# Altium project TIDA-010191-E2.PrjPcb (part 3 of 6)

## Sheet TIDA-010191-E2_CDCLVP111.SchDoc: LMK0482x
size 558 x 431 mm; Date: Not shown in title block; ApprovedBy: Not shown in title block; CheckedBy: Not shown in title block; Author: Not shown in title block; CompanyName: Not shown in title block; DrawnBy: Avinash N; Engineer: Not shown in title block; Organization: Not shown in title block; Address1: Not shown in title block; Address2: Not shown in title block; Address3: Not shown in title block; Address4: Not shown in title block; DocumentNumber: 3; Revision: Use project parameter SCH_Rev; SheetNumber: 3; SheetTotal: 9; PageSetup: Record=PageOptions¦CenterHorizontal=True¦CenterVertical=True¦PrintScale=1.00¦XCorrection=1.00¦YCorrection=1.00¦PrintKind=0¦BorderSize=5000000¦LeftOffset=0¦BottomOffset=0¦Orientation=2¦PaperLength=1000¦PaperWidth=1000¦Scale=100¦PaperSource=15¦PrintQuality=600¦MediaType=1¦DitherType=10¦PaperKind=Letter¦PrintScaleMode=1
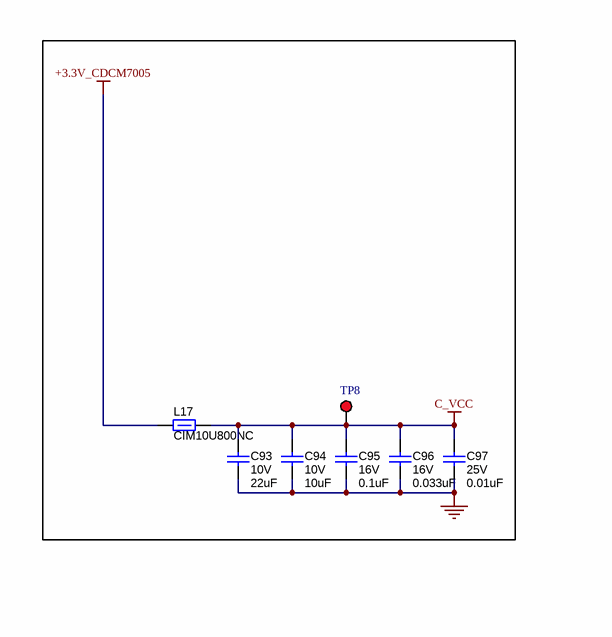
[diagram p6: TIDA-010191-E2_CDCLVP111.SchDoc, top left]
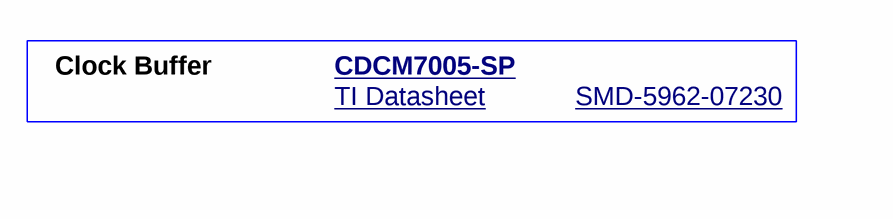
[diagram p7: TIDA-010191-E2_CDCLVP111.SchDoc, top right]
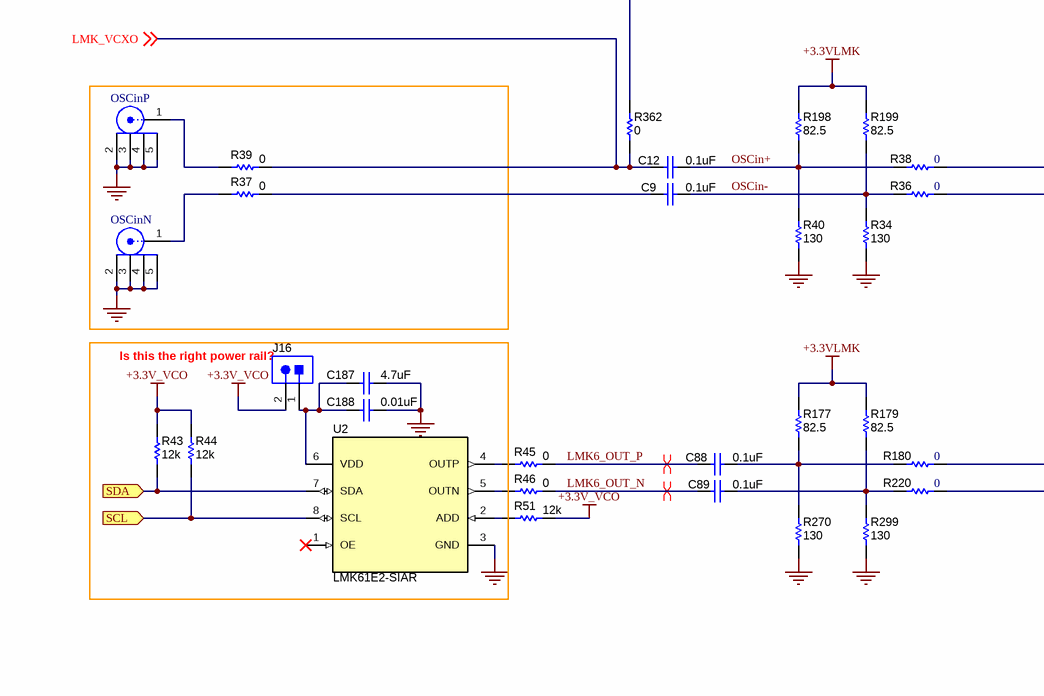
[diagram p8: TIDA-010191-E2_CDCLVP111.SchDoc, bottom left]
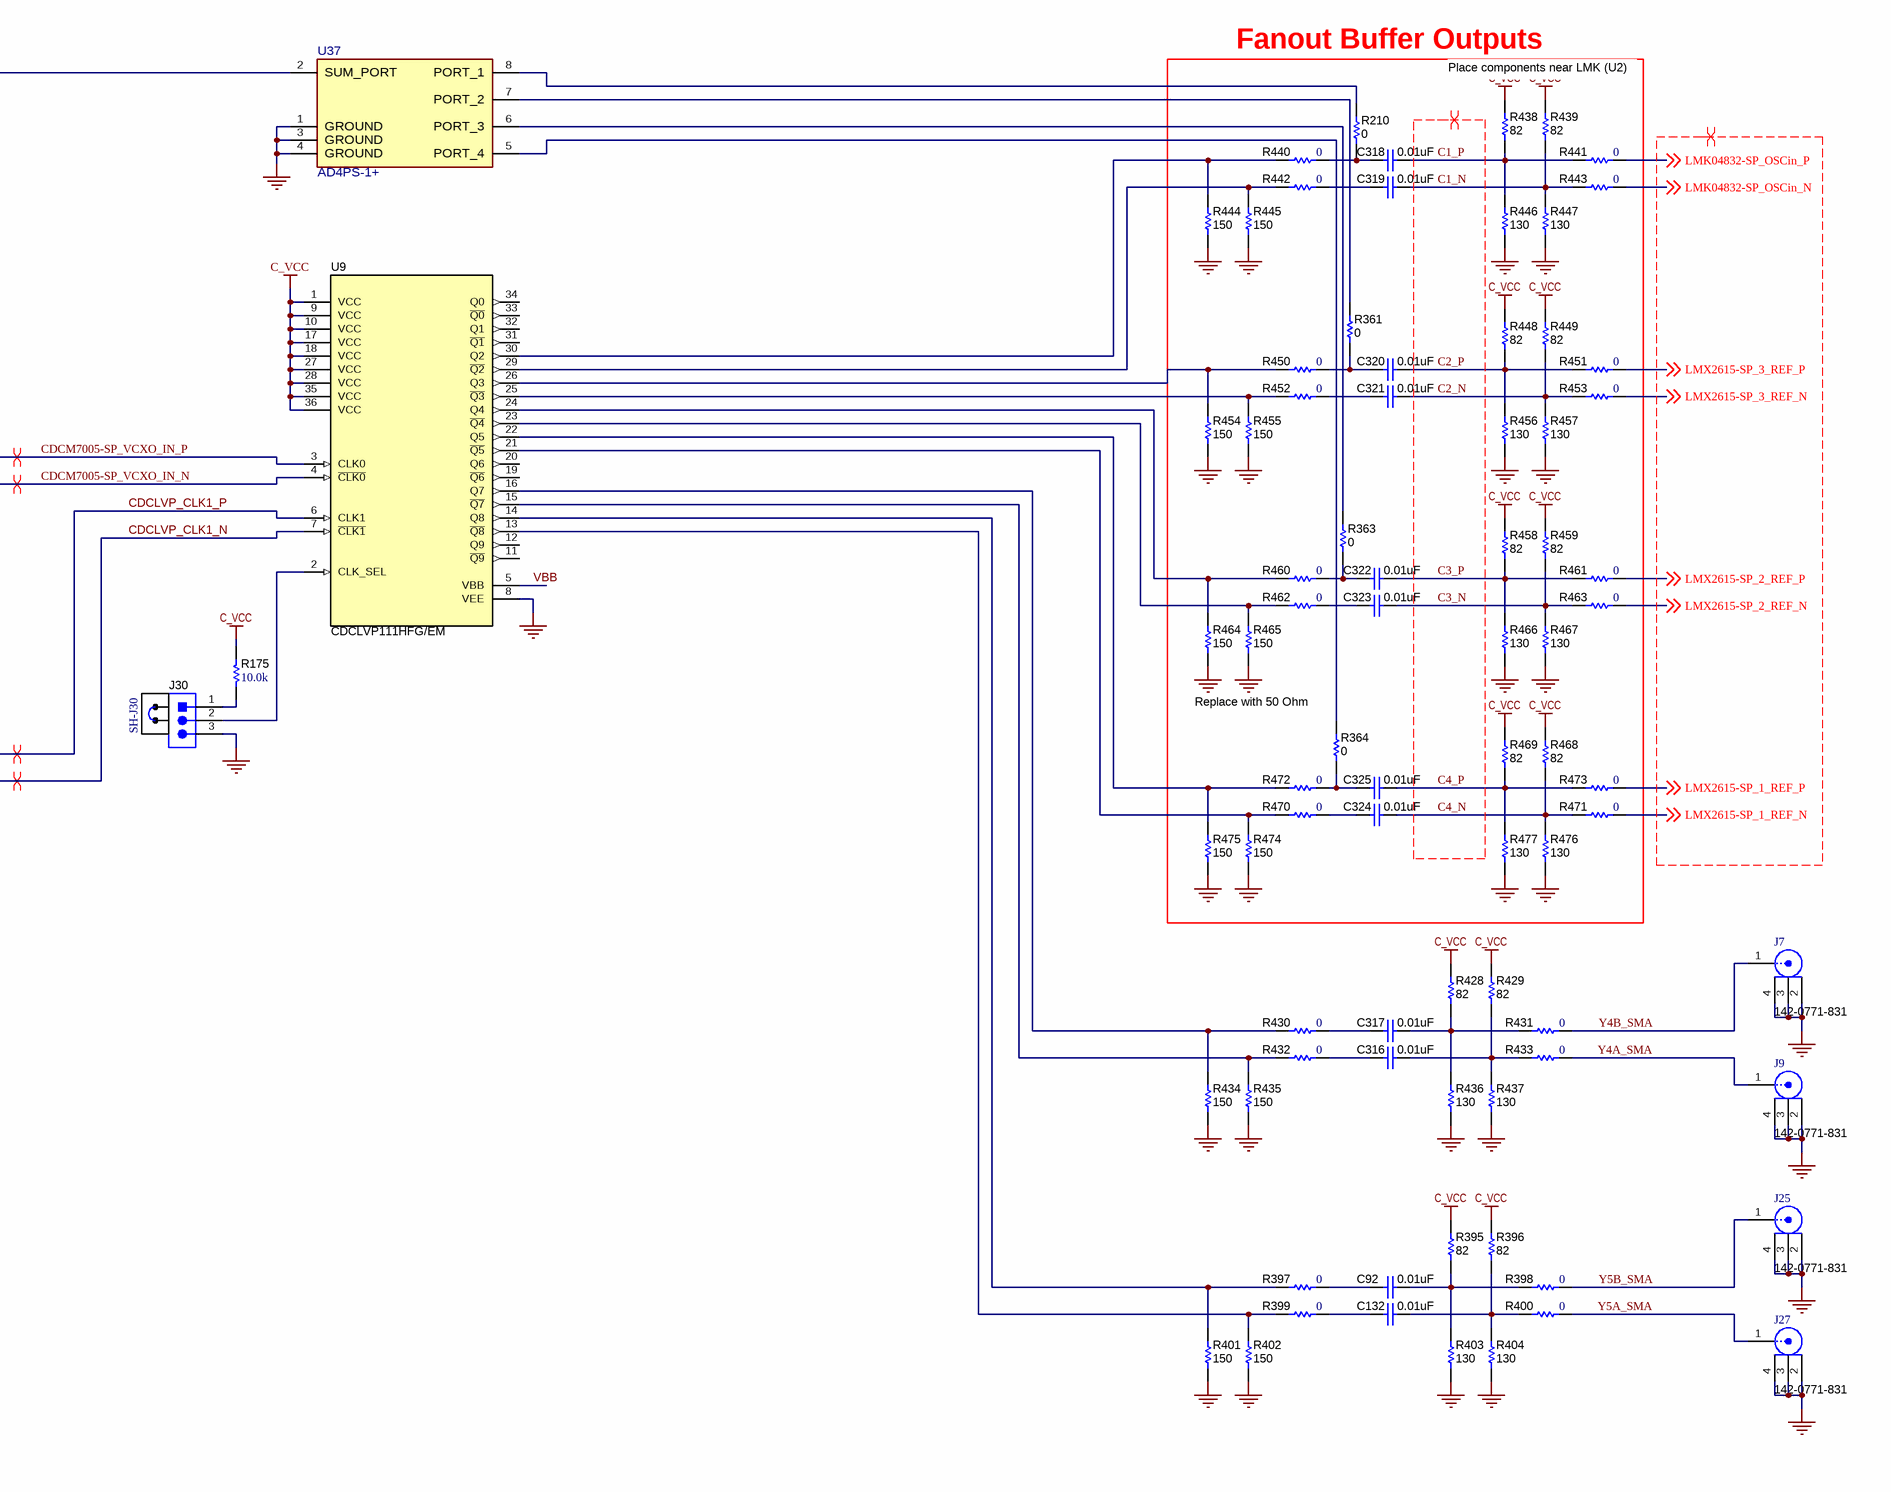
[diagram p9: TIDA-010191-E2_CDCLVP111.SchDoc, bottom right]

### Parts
C9  ValueDisplayed: 0.1uF  [0402]  (hidden comment: Capacitor)
C12  ValueDisplayed: 0.1uF  [0402]  (hidden comment: Capacitor)
C88  ValueDisplayed: 0.1uF  [0402]  (hidden comment: Capacitor)
C89  ValueDisplayed: 0.1uF  [0402]  (hidden comment: Capacitor)
C92  ValueDisplayed: 0.01uF  [0402_065]  (hidden comment: CMP-0006210-2)
C93  VDC_V: 10V  ValueDisplayed: 22uF  [1210_270]  (hidden comment: GRM32ER61A226KE20L)
C94  VDC_V: 10V  ValueDisplayed: 10uF  [1210_210]  (hidden comment: C1210C106K8PACTU)
C95  VDC_V: 16V  ValueDisplayed: 0.1uF  [0402]  (hidden comment: 885012105016)
C96  VDC_V: 16V  ValueDisplayed: 0.033uF  [0402]  (hidden comment: GRM155R61C333KA01D)
C97  VDC_V: 25V  ValueDisplayed: 0.01uF  [0402]  (hidden comment: GCM155R71E103KA37D)
C132  ValueDisplayed: 0.01uF  [0402_065]  (hidden comment: CMP-0006210-2)
C187  ValueDisplayed: 4.7uF  [0402]  (hidden comment: Capacitor)
C188  ValueDisplayed: 0.01uF  [0402]  (hidden comment: Capacitor)
C316  ValueDisplayed: 0.01uF  [0402_065]  (hidden comment: CMP-0006210-2)
C317  ValueDisplayed: 0.01uF  [0402_065]  (hidden comment: CMP-0006210-2)
C318  ValueDisplayed: 0.01uF  [0402_065]  (hidden comment: CMP-0006210-2)
C319  ValueDisplayed: 0.01uF  [0402_065]  (hidden comment: CMP-0006210-2)
C320  ValueDisplayed: 0.01uF  [0402_065]  (hidden comment: CMP-0006210-2)
C321  ValueDisplayed: 0.01uF  [0402_065]  (hidden comment: CMP-0006210-2)
C322  ValueDisplayed: 0.01uF  [0402_065]  (hidden comment: CMP-0006210-2)
C323  ValueDisplayed: 0.01uF  [0402_065]  (hidden comment: CMP-0006210-2)
C324  ValueDisplayed: 0.01uF  [0402_065]  (hidden comment: CMP-0006210-2)
C325  ValueDisplayed: 0.01uF  [0402_065]  (hidden comment: CMP-0006210-2)
J7  142-0771-831  [Johnson_142-0771-831]
J9  142-0771-831  [Johnson_142-0771-831]
J16  HTSW-102-07-G-S  [Samtec_HTSW-102-07-G-S]  (value not drawn)
J25  142-0771-831  [Johnson_142-0771-831]
J27  142-0771-831  [Johnson_142-0771-831]
J30  HTSW-103-07-G-S  [Samtec_HTSW-103-07-G-S]  (value not drawn)
L17  CIM10U800NC  [0603]
OSCinN  SMA_Contact1_GND2345  [Emerson_142-0701-851]  (value not drawn)
OSCinP  SMA_Contact1_GND2345  [Emerson_142-0701-851]  (value not drawn)
R34  ValueDisplayed: 130  [0402]  (hidden comment: Resistor)
R36  ValueDisplayed: 0  [0402]  (hidden comment: ERJ-2GE0R00X)
R37  ValueDisplayed: 0  [0402]  (hidden comment: Resistor)
R38  ValueDisplayed: 0  [0402]  (hidden comment: ERJ-2GE0R00X)
R39  ValueDisplayed: 0  [0402]  (hidden comment: Resistor)
R40  ValueDisplayed: 130  [0402]  (hidden comment: Resistor)
R43  ValueDisplayed: 12k  [0402]  (hidden comment: Resistor)
R44  ValueDisplayed: 12k  [0402]  (hidden comment: Resistor)
R45  ValueDisplayed: 0  [0402]  (hidden comment: Resistor)
R46  ValueDisplayed: 0  [0402]  (hidden comment: Resistor)
R51  ValueDisplayed: 12k  [0402]  (hidden comment: Resistor)
R175  ValueDisplayed: 10.0k  [0402]  (hidden comment: ERJ-2RKF1002X)
R177  ValueDisplayed: 82.5  [0402]  (hidden comment: CRCW040282R5FKED)
R179  ValueDisplayed: 82.5  [0402]  (hidden comment: CRCW040282R5FKED)
R180  ValueDisplayed: 0  [0402]  (hidden comment: ERJ-2GE0R00X)
R198  ValueDisplayed: 82.5  [0402]  (hidden comment: CRCW040282R5FKED)
R199  ValueDisplayed: 82.5  [0402]  (hidden comment: CRCW040282R5FKED)
R210  ValueDisplayed: 0  [0201]  (hidden comment: ERJ-1GN0R00C)
R220  ValueDisplayed: 0  [0402]  (hidden comment: ERJ-2GE0R00X)
R270  ValueDisplayed: 130  [0402]  (hidden comment: Resistor)
R299  ValueDisplayed: 130  [0402]  (hidden comment: Resistor)
R361  ValueDisplayed: 0  [0201]  (hidden comment: ERJ-1GN0R00C)
R362  ValueDisplayed: 0  [0201]  (hidden comment: ERJ-1GN0R00C)
R363  ValueDisplayed: 0  [0201]  (hidden comment: ERJ-1GN0R00C)
R364  ValueDisplayed: 0  [0201]  (hidden comment: ERJ-1GN0R00C)
R395  ValueDisplayed: 82  [0402]  (hidden comment: CRCW040282R0JNED)
R396  ValueDisplayed: 82  [0402]  (hidden comment: CRCW040282R0JNED)
R397  ValueDisplayed: 0  [0402]  (hidden comment: ERJ-2GE0R00X)
R398  ValueDisplayed: 0  [0402]  (hidden comment: ERJ-2GE0R00X)
R399  ValueDisplayed: 0  [0402]  (hidden comment: ERJ-2GE0R00X)
R400  ValueDisplayed: 0  [0402]  (hidden comment: ERJ-2GE0R00X)
R401  ValueDisplayed: 150  [0402]  (hidden comment: CRCW0402150RFKED)
R402  ValueDisplayed: 150  [0402]  (hidden comment: CRCW0402150RFKED)
R403  ValueDisplayed: 130  [0402]  (hidden comment: CRCW0402130RFKED)
R404  ValueDisplayed: 130  [0402]  (hidden comment: CRCW0402130RFKED)
R428  ValueDisplayed: 82  [0402]  (hidden comment: CRCW040282R0JNED)
R429  ValueDisplayed: 82  [0402]  (hidden comment: CRCW040282R0JNED)
R430  ValueDisplayed: 0  [0402]  (hidden comment: ERJ-2GE0R00X)
R431  ValueDisplayed: 0  [0402]  (hidden comment: ERJ-2GE0R00X)
R432  ValueDisplayed: 0  [0402]  (hidden comment: ERJ-2GE0R00X)
R433  ValueDisplayed: 0  [0402]  (hidden comment: ERJ-2GE0R00X)
R434  ValueDisplayed: 150  [0402]  (hidden comment: CRCW0402150RFKED)
R435  ValueDisplayed: 150  [0402]  (hidden comment: CRCW0402150RFKED)
R436  ValueDisplayed: 130  [0402]  (hidden comment: CRCW0402130RFKED)
R437  ValueDisplayed: 130  [0402]  (hidden comment: CRCW0402130RFKED)
R438  ValueDisplayed: 82  [0402]  (hidden comment: CRCW040282R0JNED)
R439  ValueDisplayed: 82  [0402]  (hidden comment: CRCW040282R0JNED)
R440  ValueDisplayed: 0  [0402]  (hidden comment: ERJ-2GE0R00X)
R441  ValueDisplayed: 0  [0402]  (hidden comment: ERJ-2GE0R00X)
R442  ValueDisplayed: 0  [0402]  (hidden comment: ERJ-2GE0R00X)
R443  ValueDisplayed: 0  [0402]  (hidden comment: ERJ-2GE0R00X)
R444  ValueDisplayed: 150  [0402]  (hidden comment: CRCW0402150RFKED)
R445  ValueDisplayed: 150  [0402]  (hidden comment: CRCW0402150RFKED)
R446  ValueDisplayed: 130  [0402]  (hidden comment: CRCW0402130RFKED)
R447  ValueDisplayed: 130  [0402]  (hidden comment: CRCW0402130RFKED)
R448  ValueDisplayed: 82  [0402]  (hidden comment: CRCW040282R0JNED)
R449  ValueDisplayed: 82  [0402]  (hidden comment: CRCW040282R0JNED)
R450  ValueDisplayed: 0  [0402]  (hidden comment: ERJ-2GE0R00X)
R451  ValueDisplayed: 0  [0402]  (hidden comment: ERJ-2GE0R00X)
R452  ValueDisplayed: 0  [0402]  (hidden comment: ERJ-2GE0R00X)
R453  ValueDisplayed: 0  [0402]  (hidden comment: ERJ-2GE0R00X)
R454  ValueDisplayed: 150  [0402]  (hidden comment: CRCW0402150RFKED)
R455  ValueDisplayed: 150  [0402]  (hidden comment: CRCW0402150RFKED)
R456  ValueDisplayed: 130  [0402]  (hidden comment: CRCW0402130RFKED)
R457  ValueDisplayed: 130  [0402]  (hidden comment: CRCW0402130RFKED)
R458  ValueDisplayed: 82  [0402]  (hidden comment: CRCW040282R0JNED)
R459  ValueDisplayed: 82  [0402]  (hidden comment: CRCW040282R0JNED)
R460  ValueDisplayed: 0  [0402]  (hidden comment: ERJ-2GE0R00X)
R461  ValueDisplayed: 0  [0402]  (hidden comment: ERJ-2GE0R00X)
R462  ValueDisplayed: 0  [0402]  (hidden comment: ERJ-2GE0R00X)
R463  ValueDisplayed: 0  [0402]  (hidden comment: ERJ-2GE0R00X)
R464  ValueDisplayed: 150  [0402]  (hidden comment: CRCW0402150RFKED)
R465  ValueDisplayed: 150  [0402]  (hidden comment: CRCW0402150RFKED)
R466  ValueDisplayed: 130  [0402]  (hidden comment: CRCW0402130RFKED)
R467  ValueDisplayed: 130  [0402]  (hidden comment: CRCW0402130RFKED)
R468  ValueDisplayed: 82  [0402]  (hidden comment: CRCW040282R0JNED)
R469  ValueDisplayed: 82  [0402]  (hidden comment: CRCW040282R0JNED)
R470  ValueDisplayed: 0  [0402]  (hidden comment: ERJ-2GE0R00X)
R471  ValueDisplayed: 0  [0402]  (hidden comment: ERJ-2GE0R00X)
R472  ValueDisplayed: 0  [0402]  (hidden comment: ERJ-2GE0R00X)
R473  ValueDisplayed: 0  [0402]  (hidden comment: ERJ-2GE0R00X)
R474  ValueDisplayed: 150  [0402]  (hidden comment: CRCW0402150RFKED)
R475  ValueDisplayed: 150  [0402]  (hidden comment: CRCW0402150RFKED)
R476  ValueDisplayed: 130  [0402]  (hidden comment: CRCW0402130RFKED)
R477  ValueDisplayed: 130  [0402]  (hidden comment: CRCW0402130RFKED)
SH-J30  SPC02SYAN  [SPC02SYAN]  (value not drawn)
TP8  5000  [Keystone5000]  (value not drawn)
U2  PartNumber: LMK61E2-SIAR  [SIA0008B]  (hidden comment: CMP-0075884-1)
U9  CDCLVP111HFG/EM  [HFG0036A_Custom_A]
U37  AD4PS-1+  [FP-AD4PS-1+_SMT8-MFG]

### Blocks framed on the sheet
Is this the right power rail?: C187 C188 J16 R43 R44 U2

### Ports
SCL (in), SDA (in)

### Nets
+3.3V_CDCM7005: L17.1
+3.3V_VCO: J16.2 R43.2 R44.2 R51.1
+3.3VLMK: R177.1 R179.1 R198.1 R199.1
C_VCC: C93.1 C94.1 C95.1 C96.1 C97.1 L17.2 R175.2 R395.2 R396.2 R428.2 R429.2 R438.2 R439.2 R448.2 R449.2 R458.2 R459.2 R468.2 R469.2 TP8.1 U9.1(VCC) U9.9(VCC) U9.10(VCC) U9.17(VCC) U9.18(VCC) U9.27(VCC) U9.28(VCC) U9.35(VCC) U9.36(VCC)
GND: C93.2 C94.2 C95.2 C96.2 C97.2 C187.1 C188.1 J7.2 J7.3 J7.4 J9.2 J9.3 J9.4 J25.2 J25.3 J25.4 J27.2 J27.3 J27.4 J30.3 OSCinN.2 OSCinN.3 OSCinN.4 OSCinN.5 OSCinP.2 OSCinP.3 OSCinP.4 OSCinP.5 R34.2 R40.2 R270.2 R299.2 R401.1 R402.1 R403.1 R404.1 R434.1 R435.1 R436.1 R437.1 R444.1 R445.1 R446.1 R447.1 R454.1 R455.1 R456.1 R457.1 R464.1 R465.1 R466.1 R467.1 R474.1 R475.1 R476.1 R477.1 U2.3(GND) U9.8(VEE) U37.1(GROUND) U37.3(GROUND) U37.4(GROUND)
C1_N: C319.1 R439.1 R443.1 R447.2
C1_P: C318.1 R438.1 R441.1 R446.2
C2_N: C321.1 R449.1 R453.1 R457.2
C2_P: C320.1 R448.1 R451.1 R456.2
C3_N: C323.1 R459.1 R463.1 R467.2
C3_P: C322.1 R458.1 R461.1 R466.2
C4_N: C324.1 R468.1 R471.1 R476.2
C4_P: C325.1 R469.1 R473.1 R477.2
CDCLVP_CLK1_N: R220.2 U9.7(~{CLK1})
CDCLVP_CLK1_P: R180.2 U9.6(CLK1)
CDCM7005-SP_VCXO_IN_N: R36.2 U9.4(~{CLK0})
CDCM7005-SP_VCXO_IN_P: R38.2 U9.3(CLK0)
LMK6_OUT_N: C89.1 R46.2
LMK6_OUT_P: C88.1 R45.2
LMK04832-SP_OSCin_N: R443.2 ; off-sheet LMK04832-SP_OSCin_N  [project net LMK_OSCin_N]
LMK04832-SP_OSCin_P: R441.2 ; off-sheet LMK04832-SP_OSCin_P  [project net LMK_OSCin_P]
LMK_VCXO: C12.1 R39.2 R362.1 ; off-sheet LMK_VCXO
LMX2615-SP_1_REF_N: R471.2 ; off-sheet LMX2615-SP_1_REF_N
LMX2615-SP_1_REF_P: R473.2 ; off-sheet LMX2615-SP_1_REF_P
LMX2615-SP_2_REF_N: R463.2 ; off-sheet LMX2615-SP_2_REF_N
LMX2615-SP_2_REF_P: R461.2 ; off-sheet LMX2615-SP_2_REF_P
LMX2615-SP_3_REF_N: R453.2 ; off-sheet LMX2615-SP_3_REF_N
LMX2615-SP_3_REF_P: R451.2 ; off-sheet LMX2615-SP_3_REF_P
OSCin+: C12.2 R38.1 R40.1 R198.2
OSCin-: C9.2 R34.1 R36.1 R199.2
SCL: R44.1 U2.8(SCL) ; port SCL
SDA: R43.1 U2.7(SDA) ; port SDA
VBB: U9.5(VBB)
Y4A_SMA: J9.1 R433.2
Y4B_SMA: J7.1 R431.2
Y5A_SMA: J27.1 R400.2
Y5B_SMA: J25.1 R398.2
NetC9_1: C9.1 R37.2
NetC88_2: C88.2 R177.2 R180.1 R270.1
NetC89_2: C89.2 R179.2 R220.1 R299.1
NetC92_1: C92.1 R395.1 R398.1 R403.2
NetC92_2: C92.2 R397.2
NetC132_1: C132.1 R396.1 R400.1 R404.2
NetC132_2: C132.2 R399.2
NetC187_2: C187.2 C188.2 J16.1 U2.6(VDD)
NetC316_1: C316.1 R429.1 R433.1 R437.2
NetC316_2: C316.2 R432.2
NetC317_1: C317.1 R428.1 R431.1 R436.2
NetC317_2: C317.2 R430.2
NetC318_2: C318.2 R210.1 R440.2
NetC319_2: C319.2 R442.2
NetC320_2: C320.2 R361.1 R450.2
NetC321_2: C321.2 R452.2
NetC322_2: C322.2 R363.1 R460.2
NetC323_2: C323.2 R462.2
NetC324_2: C324.2 R470.2
NetC325_2: C325.2 R364.1 R472.2
NetJ30_1: J30.1 R175.1
NetJ30_2: J30.2 U9.2(CLK_SEL)
NetOSCinN_1: OSCinN.1 R37.1
NetOSCinP_1: OSCinP.1 R39.1
NetR45_1: R45.1 U2.4(OUTP)
NetR46_1: R46.1 U2.5(OUTN)
NetR51_2: R51.2 U2.2(ADD)
NetR210_2: R210.2 U37.8(PORT_1)
NetR361_2: R361.2 U37.7(PORT_2)
NetR362_2: R362.2 U37.2(SUM_PORT)
NetR363_2: R363.2 U37.6(PORT_3)
NetR364_2: R364.2 U37.5(PORT_4)
NetR397_1: R397.1 R401.2 U9.14(Q8)
NetR399_1: R399.1 R402.2 U9.13(~{Q8})
NetR430_1: R430.1 R434.2 U9.16(Q7)
NetR432_1: R432.1 R435.2 U9.15(~{Q7})
NetR440_1: R440.1 R444.2 U9.30(Q2)
NetR442_1: R442.1 R445.2 U9.29(~{Q2})
NetR450_1: R450.1 R454.2 U9.26(Q3)
NetR452_1: R452.1 R455.2 U9.25(~{Q3})
NetR460_1: R460.1 R464.2 U9.24(Q4)
NetR462_1: R462.1 R465.2 U9.23(~{Q4})
NetR470_1: R470.1 R474.2 U9.21(~{Q5})
NetR472_1: R472.1 R475.2 U9.22(Q5)

Not connected (* = marked no-connect by the designer): U2 1(OE)*; U9 11(~{Q9}) 12(Q9) 19(~{Q6}) 20(Q6) 31(~{Q1}) 32(Q1) 33(~{Q0}) 34(Q0)

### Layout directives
differential pair: CDCLVP_CLK1_N, CDCLVP_CLK1_P, CDCM7005-SP_VCXO_IN_N, CDCM7005-SP_VCXO_IN_P, LMK6_OUT_N, LMK6_OUT_P
differential pair; differential pair class 100ohm: C1_N, C1_P, C2_N, C2_P, C3_N, C3_P, C4_N, C4_P, LMK04832-SP_OSCin_N, LMK04832-SP_OSCin_P, LMX2615-SP_1_REF_N, LMX2615-SP_1_REF_P, LMX2615-SP_2_REF_N, LMX2615-SP_2_REF_P, LMX2615-SP_3_REF_N, LMX2615-SP_3_REF_P

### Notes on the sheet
- Clock Buffer
- TI Datasheet <http://www.ti.com/lit/gpn/cdcm7005-sp>
- CDCM7005-SP <http://www.ti.com/product/CDCM7005-SP>
- SMD-5962-07230 <https://landandmaritimeapps.dla.mil/Downloads/MilSpec/Smd/07230.pdf>
- Fanout Buffer Outputs
- Place components near LMK (U2)
- (near R364) Replace with 50 Ohm

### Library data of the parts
C9 C12 C88 C89 = CMP-0006295-2: CAP, CERM, 0.1 uF, 25 V, +/- 20%, X7R, 0402; Manufacturer: TDK; PartNumber: C1005X7R1E104M050BB; Polarized: N; TaMax_C: 125°C; TaMin_C: -55°C; VDC_V: 25V; Cap_F: 100nF; Value: 0.1uF; Value1: Unknown; U/M: EA; SizeArea_mm2: 0.5; SizeAreaWB_mm2: 3; SizeX_mm: 1; SizeZ_mm: 0.6; AEC Category: Q200
C92 C132 C316-C325 = CMP-0006210-2: CAP, CERM, 0.01 uF, 16 V, +/- 10%, X7R, 0402; PartNumber: 520L103KT16T; Manufacturer: AT Ceramics; Polarized: N; Value: 0.01uF; U/M: EA; Cap_F: 10nF; Value1: Unknown; VDC_V: 16V; TaMin_C: -55°C; TaMax_C: 125°C; Cap_Case: 0402; AEC Category: Q200; SizeArea_mm2: 0.5; SizeAreaWB_mm2: 3; SizeX_mm: 1; SizeZ_mm: 0.65
C93 = CMP-0009207-2: CAP, CERM, 22 uF, 10 V, +/- 10%, X5R, 1210; Manufacturer: MuRata; TaMin_C: -55°C; ESR_ohm: 2m; Polarized: N; SizeAreaWB_mm2: 14.7; Value1: 0.002 ohm; U/M: EA; Value: 22uF; TaMax_C: 85°C; SizeZ_mm: 2.7; SizeX_mm: 3.2; SizeY_mm: 2.5; Cap_Case: 1210; SizeArea_mm2: 8; Cap_F: 22µF; AEC Category: Q200
C94 = CMP-0009080-2: CAP, CERM, 10 uF, 10 V, +/- 10%, X5R, 1210; Manufacturer: Kemet; TaMin_C: -55°C; ESR_ohm: 8m; Polarized: N; SizeAreaWB_mm2: 14.7; Value1: 0.008 ohm; U/M: EA; Value: 10uF; TaMax_C: 85°C; SizeZ_mm: 2.1; SizeX_mm: 3.2; SizeY_mm: 2.5; Cap_Case: 1210; SizeArea_mm2: 8; Cap_F: 10µF; IRMS_A: 6.9A; AEC Category: Q200
C95 = CMP-0006223-2: CAP, CERM, 0.1 uF, 16 V, +/- 20%, X5R, 0402; Manufacturer: Wurth Elektronik; TaMin_C: -55°C; Polarized: N; SizeAreaWB_mm2: 3; Value1: Unknown; U/M: EA; Value: 0.1uF; TaMax_C: 85°C; SizeZ_mm: 0.6; SizeX_mm: 1; SizeY_mm: 0.5; Cap_F: 100nF; AEC Category: Q200
C96 = CMP-0006596-2: CAP, CERM, 0.033 uF, 16 V, +/- 10%, X5R, 0402; Manufacturer: MuRata; TaMin_C: -55°C; Polarized: N; SizeAreaWB_mm2: 3; Value1: Unknown; U/M: EA; TaMax_C: 85°C; SizeZ_mm: 0.6; SizeX_mm: 1; SizeY_mm: 0.5; Cap_F: 33nF; AEC Category: Q200
C97 = CMP-0006352-2: CAP, CERM, 0.01 uF, 25 V, +/- 10%, X7R, 0402; Manufacturer: MuRata; TaMin_C: -55°C; Polarized: N; SizeAreaWB_mm2: 3; Value1: Unknown; U/M: EA; Value: 0.01uF; TaMax_C: 125°C; SizeZ_mm: 0.6; SizeX_mm: 1; SizeY_mm: 0.5; Cap_F: 10nF; AEC Category: Q200
C187 = CMP-0006258-2: CAP, CERM, 4.7 uF, 6.3 V, +/- 20%, X5R, 0402; PartNumber: C1005X5R0J475M050BC; Manufacturer: TDK; Polarized: N; Value: 4.7uF; U/M: EA; Cap_F: 4.7µF; Value1: Unknown; VDC_V: 6.3V; TaMin_C: -55°C; TaMax_C: 85°C; SizeArea_mm2: 0.5; SizeAreaWB_mm2: 3; SizeX_mm: 1; SizeZ_mm: 0.6; AEC Category: Q200
C188 = CMP-0006658-2: CAP, CERM, 0.01 uF, 25 V, +/- 10%, X7R, 0402; PartNumber: GRM155R71E103KA01D; Manufacturer: MuRata; Polarized: N; Value: 0.01uF; U/M: EA; Cap_F: 10nF; Value1: Unknown; VDC_V: 25V; TaMin_C: -55°C; TaMax_C: 125°C; SizeArea_mm2: 0.5; SizeAreaWB_mm2: 3; SizeX_mm: 1; SizeZ_mm: 0.6; AEC Category: Q200
J7 J9 J25 J27 = CMP-0055844-3: JACK, SMA, 50 Ohm, Gold, Edge Mount; Manufacturer: Cinch Connectivity; Gender: Female; Voltage_V: 170V
J16 = CMP-0075483-1: Header, 100mil, 2x1, Gold, TH; Manufacturer: Samtec; Green_REACh: Passed; CT: False; Green_Lifecycle: Active; CNHeader: True
J30 = CMP-0075484-1: Header, 100mil, 3x1, Gold, TH; Manufacturer: Samtec; Green_REACh: Passed; CT: False; Green_Lifecycle: Active; CNHeader: True
L17 = CMP-0003370-2: Ferrite Bead, 80 ohm @ 100 MHz, 0.6 A, 0603; Manufacturer: Samsung Electro-Mechanics; ZTyp@100MHz_Ohm: 80; SizeAreaWB_mm2: 4.68; DCR_ohm: 0.1; Value1: 0.1 ohm; Value: 80 ohm; Imax_A: 600mA; SizeZ_mm: 1; SizeX_mm: 1.6; SizeY_mm: 0.8; Value2: 0.6A; SizeArea_mm2: 1.28
OSCinN OSCinP = CMP-0055822-3: Connector, End launch SMA, 50 ohm, SMT; PartNumber: 142-0701-851; Manufacturer: Cinch Connectivity; Green_Lifecycle: Not Set; Green_REACh: Incomplete
R34 R40 R270 R299 = CMP-0025998-3: RES, 130, 1%, 0.063 W, AEC-Q200 Grade 0, 0402; PartNumber: CRCW0402130RFKED; Manufacturer: Vishay-Dale; Value: 130; Value_Code: 130R; Power_W: 63mW; Value2: 0.063W; VDC_V: 50V; TempCo: 100 ppm/C; SizeArea_mm2: 0.5; SizeX_mm: 1; SizeZ_mm: 0.6; EIA_Code: E96; AEC Category: Q200; AEC Qualified: Y; AEC Grade: 0
R36 R38 R180 R220 = Resistor: RES, 0, 5%, 0.063 W, 0402; Manufacturer: Panasonic; Power_W: 63mW; TempCo: 600 ppm/C; Value_Code: 0000; U/M: EA; Value: 0; EIA_Code: E24; SizeX_mm: 1; SizeY_mm: 0.5; SizeZ_mm: 0.6; Value2: 0.063W; VDC_V: 50V; AEC Category: Q200
R37 R39 R45 R46 = CMP-0026822-3: RES, 0, 5%, 0.063 W, AEC-Q200 Grade 0, 0402; PartNumber: CRCW04020000Z0ED; Manufacturer: Vishay-Dale; Value: 0; Value_Code: 0000; Power_W: 63mW; Value2: 0.063W; VDC_V: 50V; TempCo: 200 ppm/C; EIA_Code: E24; AEC Category: Q200; AEC Qualified: Y; SizeArea_mm2: 0.5; SizeX_mm: 1; SizeZ_mm: 0.6
R43 R44 R51 = CMP-0026834-3: RES, 12 k, 5%, 0.063 W, AEC-Q200 Grade 0, 0402; PartNumber: CRCW040212K0JNED; Manufacturer: Vishay-Dale; Value: 12k; Value_Code: 12k0; Power_W: 63mW; Value2: 0.063W; VDC_V: 50V; TempCo: 200 ppm/C; EIA_Code: E24; AEC Category: Q200; AEC Qualified: Y; AEC Grade: 0; SizeArea_mm2: 0.5; SizeX_mm: 1; SizeZ_mm: 0.6
R175 = CMP-0026658-1: RES, 10.0 k, 1%, 0.1 W, 0402; Manufacturer: Panasonic; Power_W: 100mW; TempCo: 100 ppm/C; Value_Code: 10k0; U/M: EA; Value: 10.0k; EIA_Code: E96; Res_ohm: 10k; SizeX_mm: 1; SizeY_mm: 0.5; SizeZ_mm: 0.6; Value2: 0.1W; VDC_V: 50V; AEC Category: Q200
R177 R179 R198 R199 = CMP-0026575-2: RES, 82.5, 1%, 0.063 W, AEC-Q200 Grade 0, 0402; Manufacturer: Vishay-Dale; Value: 82.5; Value_Code: 82R5; Power_W: 63mW; Value2: 0.063W; VDC_V: 50V; TempCo: 100 ppm/C; EIA_Code: E96; AEC Category: Q200; AEC Qualified: Y; AEC Grade: 0; SizeArea_mm2: 0.5; SizeX_mm: 1; SizeZ_mm: 0.6
R210 R361-R364 = CMP-0065361-1: RES, 0, 5%, .05 W, AEC-Q200 Grade 0, 0201; Manufacturer: Panasonic; Power_W: 50mW; Green_Lifecycle: Not Set; TempCo: ppm/C; Value_Code: 0000; Green_REACh: Incomplete; U/M: EA; Value: 0; EIA_Code: E24; SizeX_mm: 0.6; SizeY_mm: 0.3; SizeZ_mm: 0.26; Value2: .05W; SizeArea_mm2: 0.18; AEC Qualified: Y; AEC Category: Q200
R395 R396 R428 R429 R438 R439 R448 R449 R458 R459 R468 R469 = CMP-0026981-3: RES, 82, 5%, 0.063 W, AEC-Q200 Grade 0, 0402; Manufacturer: Vishay-Dale; Power_W: 63mW; TempCo: 200 ppm/C; Value_Code: 82R0; Value: 82; EIA_Code: E24; SizeX_mm: 1; SizeY_mm: 0.5; SizeZ_mm: 0.6; Value2: 0.063W; AEC Qualified: Y; VDC_V: 50V; AEC Category: Q200; AEC Grade: 0
R397-R400 R430-R433 R440-R443 R450-R453 R460-R463 R470-R473 = CMP-0026992-3: RES, 0, 5%, 0.1 W, AEC-Q200 Grade 0, 0402; Manufacturer: Panasonic; Power_W: 100mW; TempCo: 600 ppm/C; Value_Code: 0000; Value: 0; EIA_Code: E24; SizeX_mm: 1; SizeY_mm: 0.5; SizeZ_mm: 0.6; Value2: 0.1W; AEC Qualified: Y; VDC_V: 50V; AEC Category: Q200; SizeAreaWB_mm2: 3
R401 R402 R434 R435 R444 R445 R454 R455 R464 R465 R474 R475 = CMP-0026022-3: RES, 150, 1%, 0.063 W, AEC-Q200 Grade 0, 0402; Manufacturer: Vishay-Dale; Power_W: 63mW; TempCo: 100 ppm/C; Value_Code: 150R; Value: 150; EIA_Code: E96; SizeX_mm: 1; SizeY_mm: 0.5; SizeZ_mm: 0.6; Value2: 0.063W; AEC Qualified: Y; VDC_V: 50V; AEC Category: Q200; AEC Grade: 0
R403 R404 R436 R437 R446 R447 R456 R457 R466 R467 R476 R477 = CMP-0025998-3: RES, 130, 1%, 0.063 W, AEC-Q200 Grade 0, 0402; Manufacturer: Vishay-Dale; Power_W: 63mW; TempCo: 100 ppm/C; Value_Code: 130R; Value: 130; EIA_Code: E96; SizeX_mm: 1; SizeY_mm: 0.5; SizeZ_mm: 0.6; Value2: 0.063W; AEC Qualified: Y; VDC_V: 50V; AEC Category: Q200; AEC Grade: 0
SH-J30 = CMP-0003642-1: Shunt, 100mil, Flash Gold, Black; Manufacturer: Sullins Connector Solutions; Value: 1x2
TP8 = CMP-0055137-2: Test Point, Miniature, Red, TH; Manufacturer: Keystone Electronics; ContactFinish: Silver; CNHeader: FALSE; CT: TRUE; Green_Lifecycle: Active; Green_REACh: Passed
U2 = CMP-0075884-1: Ultra-Low Jitter Fully Programmable Oscillator, Integrated EEPROM, +/-50ppm, SIA0008B (QFM-8); Alternate PartNumber: LMK61E2-SIAT; Manufacturer: Texas Instruments; CompType: IC; U/M: EA; SizeAreaWB_mm2: 20.25; SizeArea_mm2: 12.25; SizeZ_mm: 2.0; SizeY_mm: 3.5
U9 = CMP-0081033-1: Low-Voltage 1:10 LVPECL With Selectable Input Clock Driver, HFG0036A (CFP-36); Manufacturer: Texas Instruments; SizeZ_mm: 2.01443; AEC Category: Q200; AEC Qualified: N; CompType: IC
U37 = CMP-0089709-1: Power Divider, 4 Way-0 , 0.001 to 0.5 GHz, 50 ohms, SMT; Manufacturer: Mini-Circuits; AEC Qualified: No; SizeZ_mm: 5.46mm

## Sheet TIDA-010191-E2_LMX2615.SchDoc: LMX2594R
size 558 x 431 mm; Date: Not shown in title block; ApprovedBy: Not shown in title block; CheckedBy: Not shown in title block; Author: Not shown in title block; CompanyName: Not shown in title block; DrawnBy: Avinash N; Engineer: Not shown in title block; Organization: Not shown in title block; Address1: Not shown in title block; Address2: Not shown in title block; Address3: Not shown in title block; Address4: Not shown in title block; DocumentNumber: 4; Revision: Use project parameter SCH_Rev; SheetNumber: 4; SheetTotal: 9; PageSetup: Record=PageOptions¦CenterHorizontal=True¦CenterVertical=True¦PrintScale=1.00¦XCorrection=1.00¦YCorrection=1.00¦PrintKind=0¦BorderSize=5000000¦LeftOffset=0¦BottomOffset=0¦Orientation=2¦PaperLength=1000¦PaperWidth=1000¦Scale=100¦PaperSource=15¦PrintQuality=600¦MediaType=1¦DitherType=10¦PaperKind=Letter¦PrintScaleMode=1
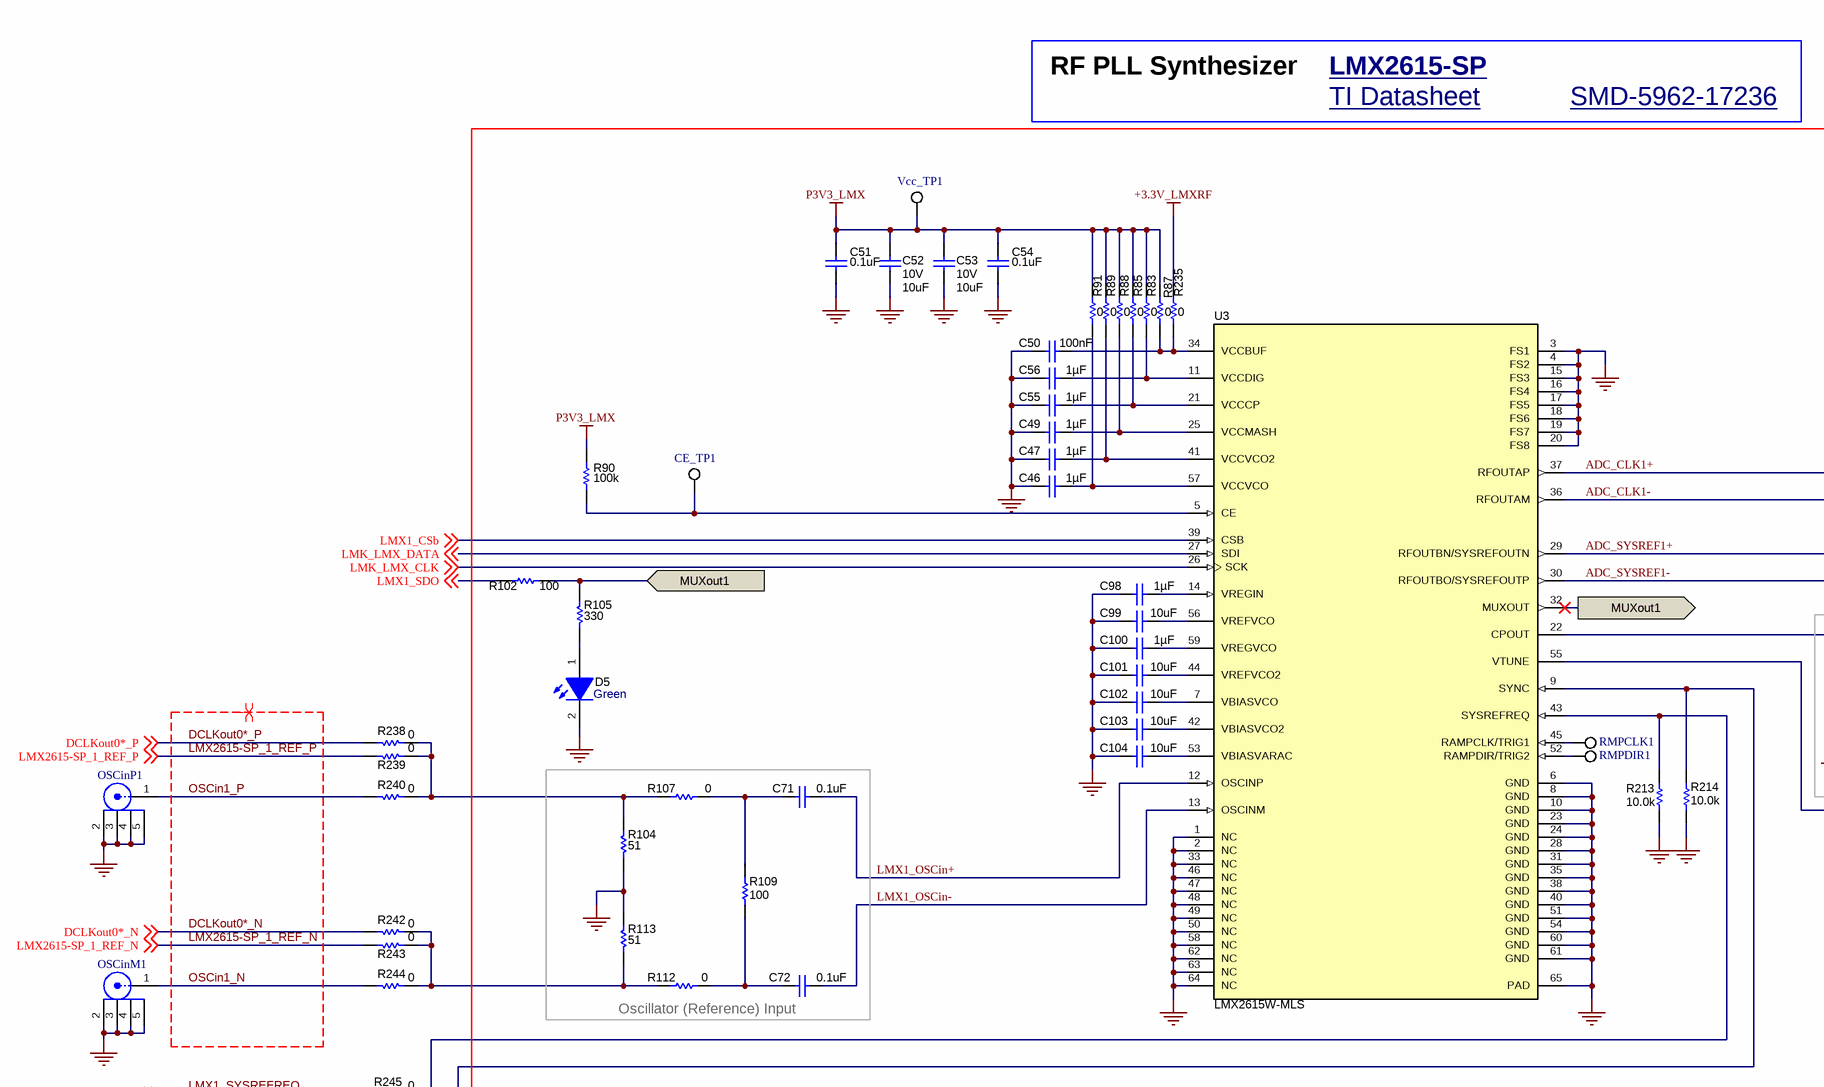
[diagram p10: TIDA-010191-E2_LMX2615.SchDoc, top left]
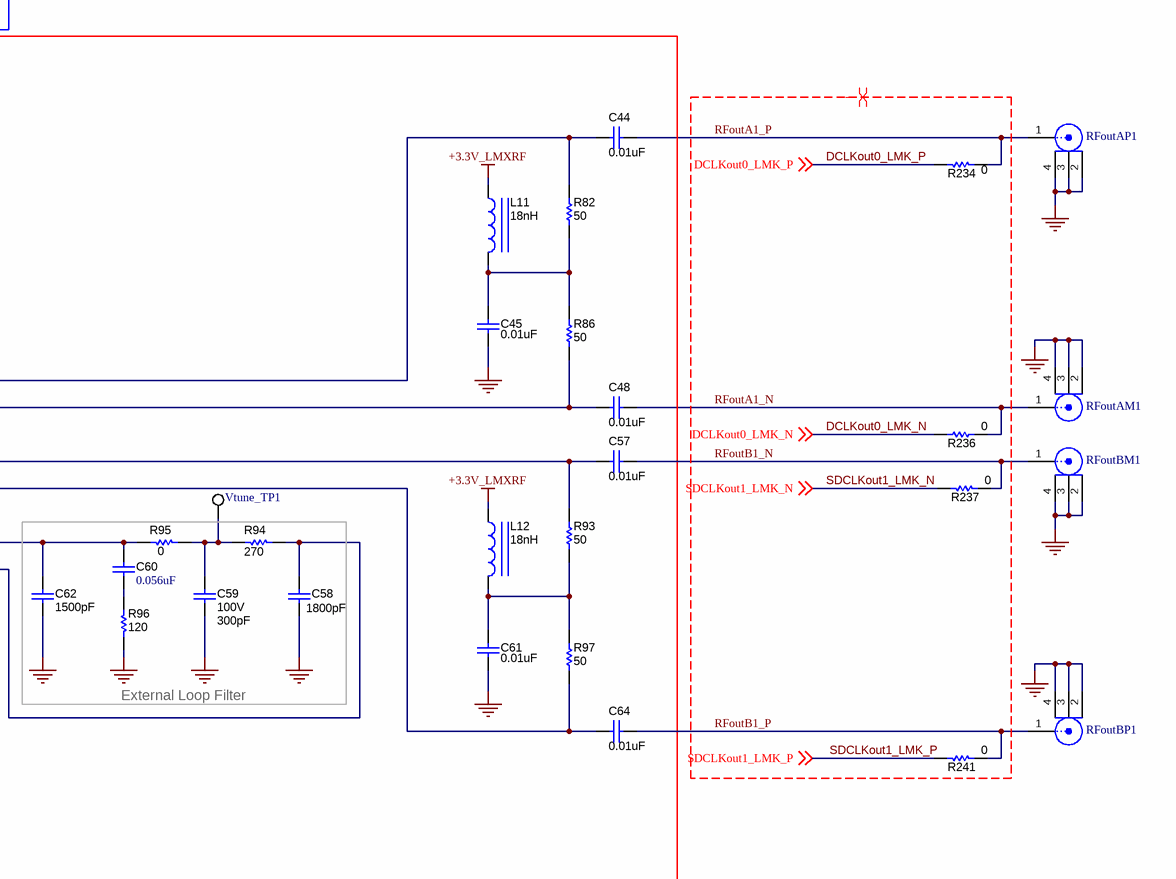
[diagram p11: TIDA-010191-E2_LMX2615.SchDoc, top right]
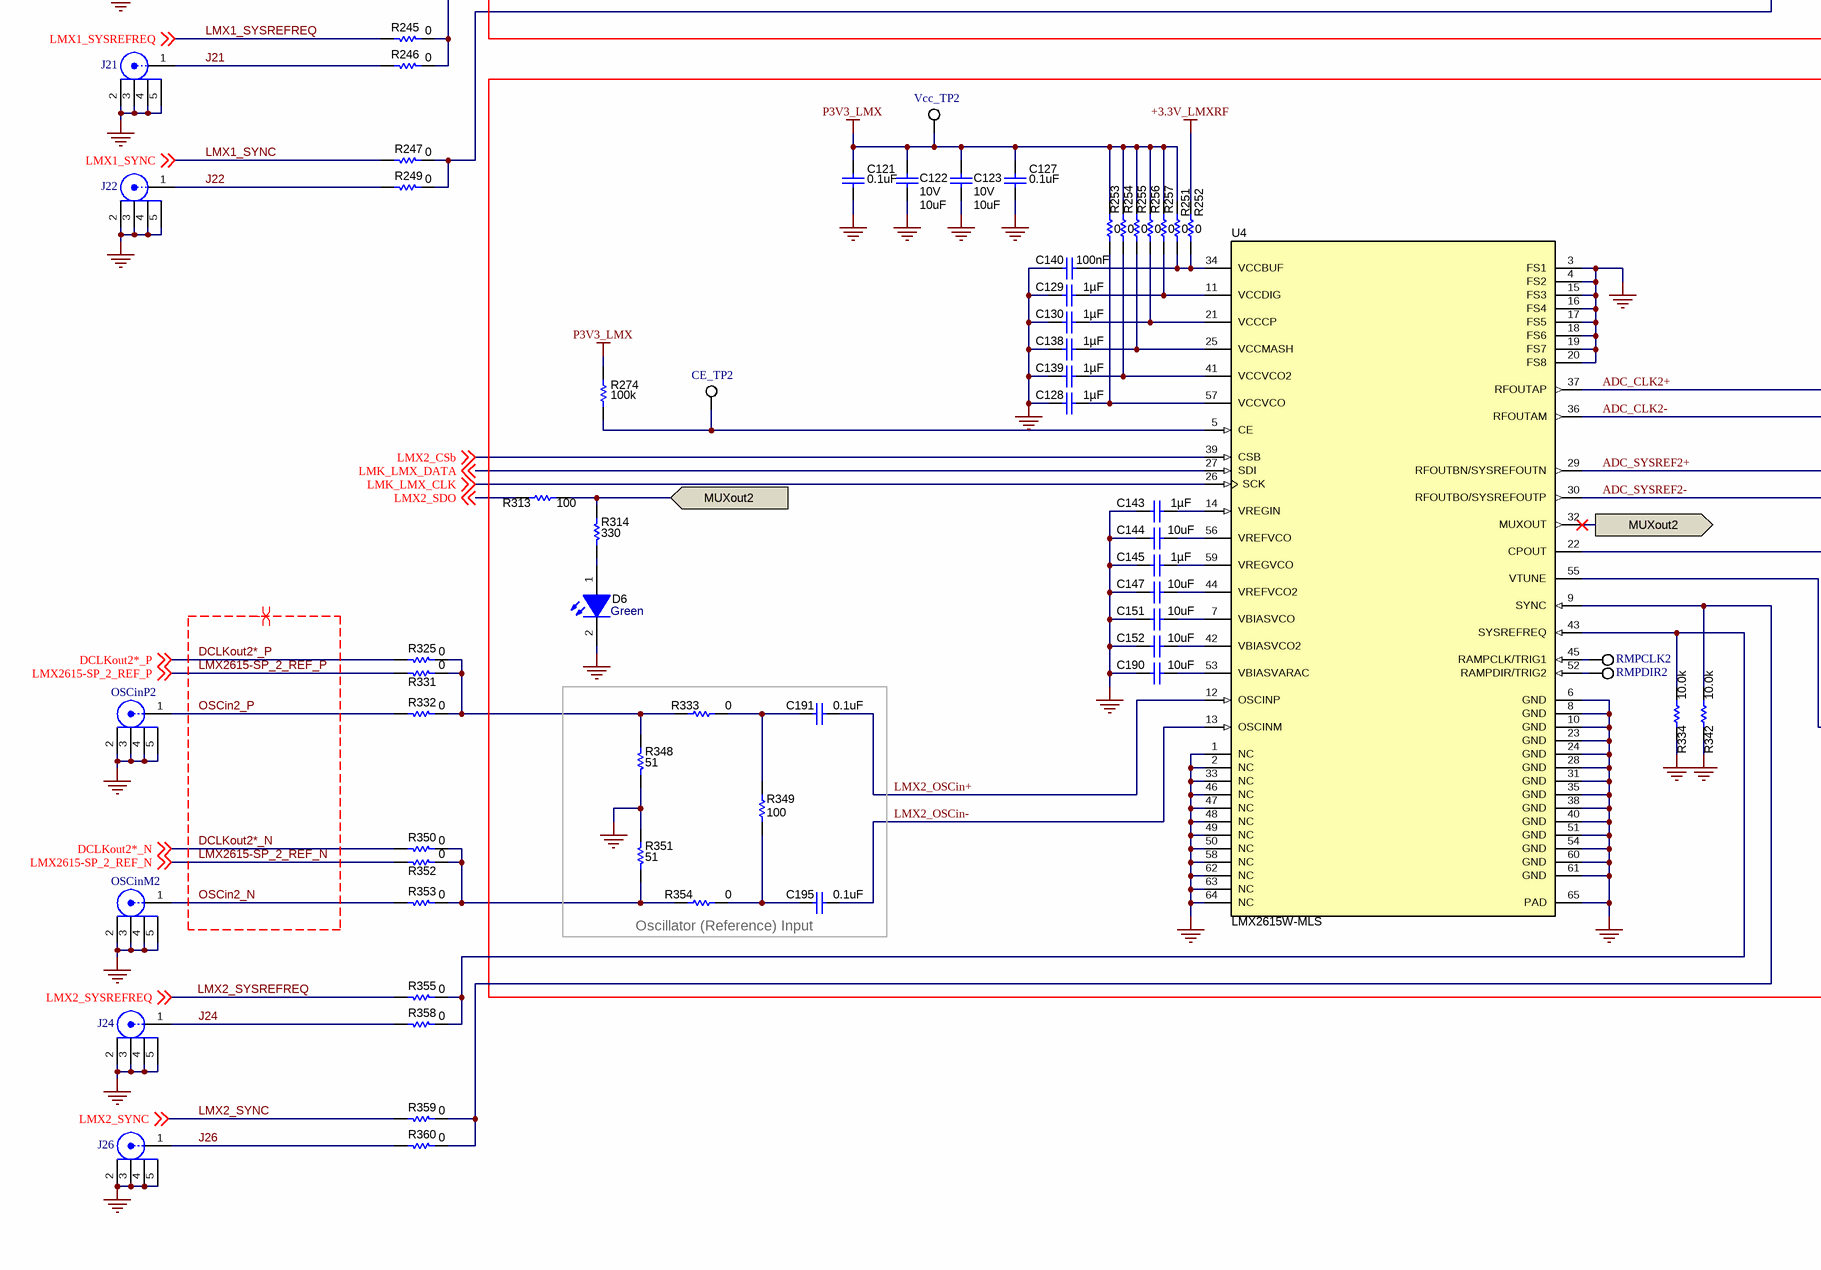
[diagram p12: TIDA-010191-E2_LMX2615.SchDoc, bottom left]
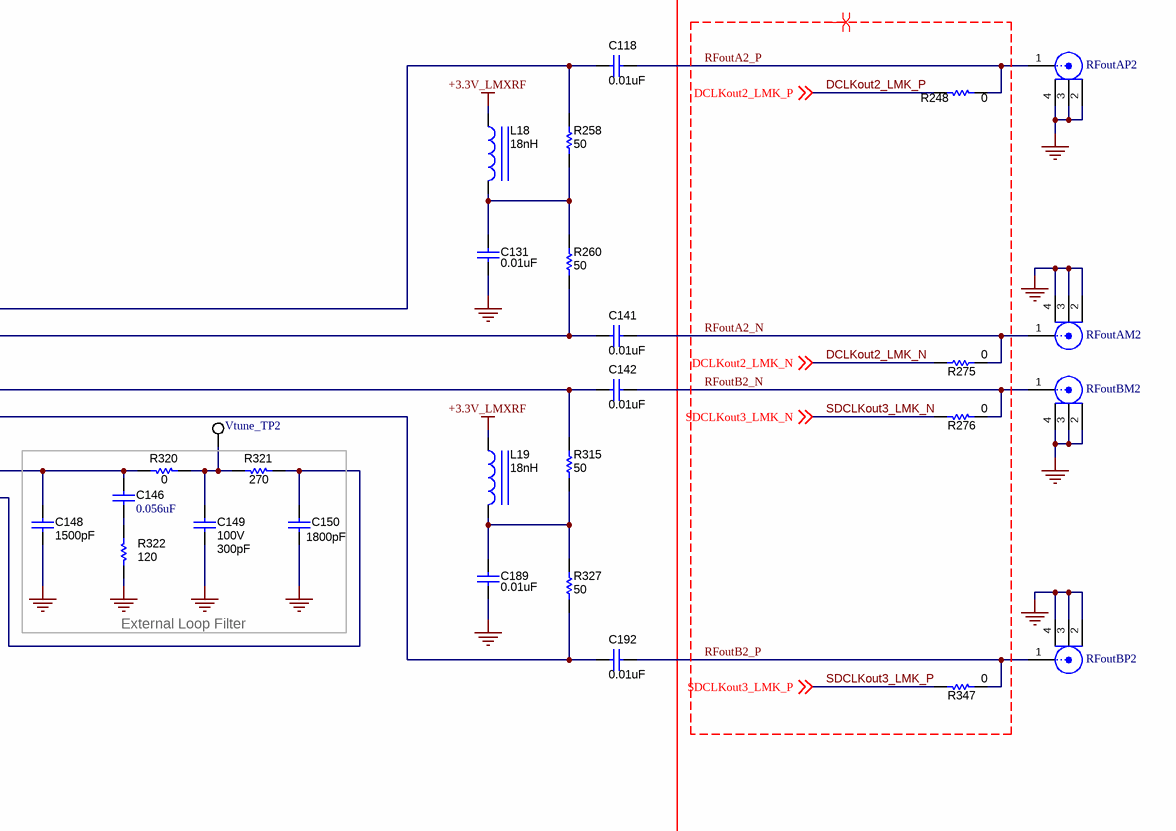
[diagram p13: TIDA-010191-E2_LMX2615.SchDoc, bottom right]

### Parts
C44  ValueDisplayed: 0.01uF  [0402_065]  (hidden comment: Capacitor)
C45  ValueDisplayed: 0.01uF  [0402_065]  (hidden comment: Capacitor)
C46  Cap_F: 1µF  [0603]  (hidden comment: CMP-0007037-4)
C47  Cap_F: 1µF  [0603]  (hidden comment: CMP-0007037-4)
C48  ValueDisplayed: 0.01uF  [0402_065]  (hidden comment: Capacitor)
C49  Cap_F: 1µF  [0603]  (hidden comment: CMP-0007037-4)
C50  Cap_F: 100nF  [0603]  (hidden comment: CMP-0006808-4)
C51  ValueDisplayed: 0.1uF  [0603]  (hidden comment: Capacitor)
C52  VDC_V: 10V  ValueDisplayed: 10uF  [0805_HV]  (hidden comment: CMP-0007732-2)
C53  VDC_V: 10V  ValueDisplayed: 10uF  [0805_HV]  (hidden comment: CMP-0007732-2)
C54  ValueDisplayed: 0.1uF  [0603]  (hidden comment: Capacitor)
C55  Cap_F: 1µF  [0603]  (hidden comment: CMP-0007037-4)
C56  Cap_F: 1µF  [0603]  (hidden comment: CMP-0007037-4)
C57  ValueDisplayed: 0.01uF  [0402_065]  (hidden comment: Capacitor)
C58  ValueDisplayed: 1800pF  [0603]  (hidden comment: Capacitor)
C59  VDC_V: 100V  ValueDisplayed: 300pF  [0603]  (hidden comment: CMP-0007262-4)
C60  ValueDisplayed: 0.056uF  [0603]  (hidden comment: Capacitor)
C61  ValueDisplayed: 0.01uF  [0402_065]  (hidden comment: Capacitor)
C62  ValueDisplayed: 1500pF  [0603]  (hidden comment: Capacitor)
C64  ValueDisplayed: 0.01uF  [0402_065]  (hidden comment: Capacitor)
C71  ValueDisplayed: 0.1uF  [0603L]  (hidden comment: Capacitor)
C72  ValueDisplayed: 0.1uF  [0603L]  (hidden comment: Capacitor)
C98  Cap_F: 1µF  [0603]  (hidden comment: CMP-0007037-4)
C99  ValueDisplayed: 10uF  [0603]  (hidden comment: CMP-0007003-5)
C100  Cap_F: 1µF  [0603]  (hidden comment: CMP-0007037-4)
C101  ValueDisplayed: 10uF  [0603]  (hidden comment: CMP-0007003-5)
C102  ValueDisplayed: 10uF  [0603]  (hidden comment: CMP-0007003-5)
C103  ValueDisplayed: 10uF  [0603]  (hidden comment: CMP-0007003-5)
C104  ValueDisplayed: 10uF  [0603]  (hidden comment: CMP-0007003-5)
C118  ValueDisplayed: 0.01uF  [0402_065]  (hidden comment: Capacitor)
C121  ValueDisplayed: 0.1uF  [0603]  (hidden comment: Capacitor)
C122  VDC_V: 10V  ValueDisplayed: 10uF  [0805_HV]  (hidden comment: CMP-0007732-2)
C123  VDC_V: 10V  ValueDisplayed: 10uF  [0805_HV]  (hidden comment: CMP-0007732-2)
C127  ValueDisplayed: 0.1uF  [0603]  (hidden comment: Capacitor)
C128  Cap_F: 1µF  [0603]  (hidden comment: CMP-0007037-4)
C129  Cap_F: 1µF  [0603]  (hidden comment: CMP-0007037-4)
C130  Cap_F: 1µF  [0603]  (hidden comment: CMP-0007037-4)
C131  ValueDisplayed: 0.01uF  [0402_065]  (hidden comment: Capacitor)
C138  Cap_F: 1µF  [0603]  (hidden comment: CMP-0007037-4)
C139  Cap_F: 1µF  [0603]  (hidden comment: CMP-0007037-4)
C140  Cap_F: 100nF  [0603]  (hidden comment: CMP-0006808-4)
C141  ValueDisplayed: 0.01uF  [0402_065]  (hidden comment: Capacitor)
C142  ValueDisplayed: 0.01uF  [0402_065]  (hidden comment: Capacitor)
C143  Cap_F: 1µF  [0603]  (hidden comment: CMP-0007037-4)
C144  ValueDisplayed: 10uF  [0603]  (hidden comment: CMP-0007003-5)
C145  Cap_F: 1µF  [0603]  (hidden comment: CMP-0007037-4)
C146  ValueDisplayed: 0.056uF  [0603]  (hidden comment: Capacitor)
C147  ValueDisplayed: 10uF  [0603]  (hidden comment: CMP-0007003-5)
C148  ValueDisplayed: 1500pF  [0603]  (hidden comment: Capacitor)
C149  VDC_V: 100V  ValueDisplayed: 300pF  [0603]  (hidden comment: CMP-0007262-4)
C150  ValueDisplayed: 1800pF  [0603]  (hidden comment: Capacitor)
C151  ValueDisplayed: 10uF  [0603]  (hidden comment: CMP-0007003-5)
C152  ValueDisplayed: 10uF  [0603]  (hidden comment: CMP-0007003-5)
C189  ValueDisplayed: 0.01uF  [0402_065]  (hidden comment: Capacitor)
C190  ValueDisplayed: 10uF  [0603]  (hidden comment: CMP-0007003-5)
C191  ValueDisplayed: 0.1uF  [0603L]  (hidden comment: Capacitor)
C192  ValueDisplayed: 0.01uF  [0402_065]  (hidden comment: Capacitor)
C195  ValueDisplayed: 0.1uF  [0603L]  (hidden comment: Capacitor)
CE_TP1  5007  [Keystone5007]  (value not drawn)
CE_TP2  5007  [Keystone5007]  (value not drawn)
D5  value Green  [LTST-C191_Green]  (hidden comment: CMP-0002891-3)
D6  value Green  [LTST-C191_Green]  (hidden comment: CMP-0002891-3)
J21  142-0701-201  [Johnson_142-0701-20x]  (value not drawn)
J22  142-0701-201  [Johnson_142-0701-20x]  (value not drawn)
J24  142-0701-201  [Johnson_142-0701-20x]  (value not drawn)
J26  142-0701-201  [Johnson_142-0701-20x]  (value not drawn)
L11  ValueDisplayed: 18nH  [IND_LQG15H]  (hidden comment: CMP-0058614-1)
L12  ValueDisplayed: 18nH  [IND_LQG15H]  (hidden comment: CMP-0058614-1)
L18  ValueDisplayed: 18nH  [IND_LQG15H]  (hidden comment: CMP-0058614-1)
L19  ValueDisplayed: 18nH  [IND_LQG15H]  (hidden comment: CMP-0058614-1)
OSCinM1  142-0701-201  [Johnson_142-0701-20x]  (value not drawn)
OSCinM2  142-0701-201  [Johnson_142-0701-20x]  (value not drawn)
OSCinP1  142-0701-201  [Johnson_142-0701-20x]  (value not drawn)
OSCinP2  142-0701-201  [Johnson_142-0701-20x]  (value not drawn)
R82  ValueDisplayed: 50  [0402]  (hidden comment: CMP-0026791-1)
R83  value 0  [0603]  (hidden comment: Resistor)
R85  value 0  [0603L]  (hidden comment: Resistor)
R86  ValueDisplayed: 50  [0402]  (hidden comment: CMP-0026791-1)
R87  value 0  [0603]  (hidden comment: Resistor)
R88  value 0  [0603L]  (hidden comment: Resistor)
R89  value 0  [0603]  (hidden comment: Resistor)
R90  ValueDisplayed: 100k  [0603]  (hidden comment: Resistor)
R91  value 0  [0603]  (hidden comment: Resistor)
R93  ValueDisplayed: 50  [0402]  (hidden comment: CMP-0026791-1)
R94  ValueDisplayed: 270  [0603]  (hidden comment: Resistor)
R95  ValueDisplayed: 0  [0603]  (hidden comment: CMP-0025697-4)
R96  ValueDisplayed: 120  [0603]  (hidden comment: Resistor)
R97  ValueDisplayed: 50  [0402]  (hidden comment: CMP-0026791-1)
R102  ValueDisplayed: 100  [0603]  (hidden comment: CMP-0021991-4)
R104  ValueDisplayed: 51  [0603]  (hidden comment: Resistor)
R105  value 330  [0603]  (hidden comment: Resistor)
R107  ValueDisplayed: 0  [0603]  (hidden comment: Resistor)
R109  ValueDisplayed: 100  [0603]  (hidden comment: CMP-0021991-4)
R112  ValueDisplayed: 0  [0603]  (hidden comment: Resistor)
R113  ValueDisplayed: 51  [0603]  (hidden comment: Resistor)
R213  ValueDisplayed: 10.0k  [0402]  (hidden comment: Resistor)
R214  ValueDisplayed: 10.0k  [0402]  (hidden comment: Resistor)
R234  ValueDisplayed: 0  [0402]  (hidden comment: Resistor)
R235  value 0  [0603]  (hidden comment: Resistor)
R236  ValueDisplayed: 0  [0402]  (hidden comment: Resistor)
R237  ValueDisplayed: 0  [0402]  (hidden comment: Resistor)
R238  ValueDisplayed: 0  [0402]  (hidden comment: CMP-0026822-3)
R239  ValueDisplayed: 0  [0402]  (hidden comment: CMP-0026822-3)
R240  ValueDisplayed: 0  [0402]  (hidden comment: CMP-0026822-3)
R241  ValueDisplayed: 0  [0402]  (hidden comment: Resistor)
R242  ValueDisplayed: 0  [0402]  (hidden comment: CMP-0026822-3)
R243  ValueDisplayed: 0  [0402]  (hidden comment: CMP-0026822-3)
R244  ValueDisplayed: 0  [0402]  (hidden comment: CMP-0026822-3)
R245  ValueDisplayed: 0  [0402]  (hidden comment: CMP-0026822-3)
R246  ValueDisplayed: 0  [0402]  (hidden comment: CMP-0026822-3)
R247  ValueDisplayed: 0  [0402]  (hidden comment: CMP-0026822-3)
R248  ValueDisplayed: 0  [0402]  (hidden comment: Resistor)
R249  ValueDisplayed: 0  [0402]  (hidden comment: CMP-0026822-3)
R251  value 0  [0603]  (hidden comment: Resistor)
R252  value 0  [0603]  (hidden comment: Resistor)
R253  value 0  [0603]  (hidden comment: Resistor)
R254  value 0  [0603]  (hidden comment: Resistor)
R255  value 0  [0603L]  (hidden comment: Resistor)
R256  value 0  [0603L]  (hidden comment: Resistor)
R257  value 0  [0603]  (hidden comment: Resistor)
R258  ValueDisplayed: 50  [0402]  (hidden comment: CMP-0026791-1)
R260  ValueDisplayed: 50  [0402]  (hidden comment: CMP-0026791-1)
R274  ValueDisplayed: 100k  [0603]  (hidden comment: Resistor)
R275  ValueDisplayed: 0  [0402]  (hidden comment: Resistor)
R276  ValueDisplayed: 0  [0402]  (hidden comment: Resistor)
R313  ValueDisplayed: 100  [0603]  (hidden comment: CMP-0021991-4)
R314  value 330  [0603]  (hidden comment: Resistor)
R315  ValueDisplayed: 50  [0402]  (hidden comment: CMP-0026791-1)
R320  ValueDisplayed: 0  [0603]  (hidden comment: CMP-0025697-4)
R321  ValueDisplayed: 270  [0603]  (hidden comment: Resistor)
R322  ValueDisplayed: 120  [0603]  (hidden comment: Resistor)
R325  ValueDisplayed: 0  [0402]  (hidden comment: CMP-0026822-3)
R327  ValueDisplayed: 50  [0402]  (hidden comment: CMP-0026791-1)
R331  ValueDisplayed: 0  [0402]  (hidden comment: CMP-0026822-3)
R332  ValueDisplayed: 0  [0402]  (hidden comment: CMP-0026822-3)
R333  ValueDisplayed: 0  [0603]  (hidden comment: Resistor)
R334  ValueDisplayed: 10.0k  [0402]  (hidden comment: CRCW040210K0DHEDP)
R342  ValueDisplayed: 10.0k  [0402]  (hidden comment: CMP-0026769-2)
R347  ValueDisplayed: 0  [0402]  (hidden comment: Resistor)
R348  ValueDisplayed: 51  [0603]  (hidden comment: Resistor)
R349  ValueDisplayed: 100  [0603]  (hidden comment: CMP-0021991-4)
R350  ValueDisplayed: 0  [0402]  (hidden comment: CMP-0026822-3)
R351  ValueDisplayed: 51  [0603]  (hidden comment: Resistor)
R352  ValueDisplayed: 0  [0402]  (hidden comment: CMP-0026822-3)
R353  ValueDisplayed: 0  [0402]  (hidden comment: CMP-0026822-3)
R354  ValueDisplayed: 0  [0603]  (hidden comment: Resistor)
R355  ValueDisplayed: 0  [0402]  (hidden comment: CMP-0026822-3)
R358  ValueDisplayed: 0  [0402]  (hidden comment: CMP-0026822-3)
R359  ValueDisplayed: 0  [0402]  (hidden comment: CMP-0026822-3)
R360  ValueDisplayed: 0  [0402]  (hidden comment: CMP-0026822-3)
RFoutAM1  142-0771-831  [Johnson_142-0771-831]  (value not drawn)
RFoutAM2  142-0771-831  [Johnson_142-0771-831]  (value not drawn)
RFoutAP1  142-0771-831  [Johnson_142-0771-831]  (value not drawn)
RFoutAP2  142-0771-831  [Johnson_142-0771-831]  (value not drawn)
RFoutBM1  142-0771-831  [Johnson_142-0771-831]  (value not drawn)
RFoutBM2  142-0771-831  [Johnson_142-0771-831]  (value not drawn)
RFoutBP1  142-0771-831  [Johnson_142-0771-831]  (value not drawn)
RFoutBP2  142-0771-831  [Johnson_142-0771-831]  (value not drawn)
RMPCLK1  5007  [Keystone5007]  (value not drawn)
RMPCLK2  5007  [Keystone5007]  (value not drawn)
RMPDIR1  5007  [Keystone5007]  (value not drawn)
RMPDIR2  5007  [Keystone5007]  (value not drawn)
U3  LMX2615W-MLS  [HBD0064A_Custom_A]
U4  LMX2615W-MLS  [HBD0064A_Custom_A]
Vcc_TP1  5007  [Keystone5007]  (value not drawn)
Vcc_TP2  5007  [Keystone5007]  (value not drawn)
Vtune_TP1  5007  [Keystone5007]  (value not drawn)
Vtune_TP2  5007  [Keystone5007]  (value not drawn)

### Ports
MUXout1 (in), MUXout1 (out), MUXout2 (in), MUXout2 (out)

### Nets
+3.3V_LMXRF: L11.1 L12.1 L18.1 L19.1 R235.1 R252.1
GND: C45.2 C46.1 C47.1 C49.1 C50.1 C51.1 C52.1 C53.1 C54.1 C55.1 C56.1 C58.1 C59.2 C61.2 C62.2 C98.1 C99.2 C100.1 C101.2 C102.2 C103.2 C104.2 C121.1 C122.1 C123.1 C127.1 C128.1 C129.1 C130.1 C131.1 C138.1 C139.1 C140.1 C143.1 C144.2 C145.1 C147.2 C148.2 C149.2 C150.1 C151.2 C152.2 C189.1 C190.2 D5.2(K) D6.2(K) J21.2 J21.3 J21.4 J21.5 J22.2 J22.3 J22.4 J22.5 J24.2 J24.3 J24.4 J24.5 J26.2 J26.3 J26.4 J26.5 OSCinM1.2 OSCinM1.3 OSCinM1.4 OSCinM1.5 OSCinM2.2 OSCinM2.3 OSCinM2.4 OSCinM2.5 OSCinP1.2 OSCinP1.3 OSCinP1.4 OSCinP1.5 OSCinP2.2 OSCinP2.3 OSCinP2.4 OSCinP2.5 R96.2 R104.2 R113.1 R213.2 R214.2 R322.2 R334.2 R342.2 R348.2 R351.1 RFoutAM1.2 RFoutAM1.3 RFoutAM1.4 RFoutAM2.2 RFoutAM2.3 RFoutAM2.4 RFoutAP1.2 RFoutAP1.3 RFoutAP1.4 RFoutAP2.2 RFoutAP2.3 RFoutAP2.4 RFoutBM1.2 RFoutBM1.3 RFoutBM1.4 RFoutBM2.2 RFoutBM2.3 RFoutBM2.4 RFoutBP1.2 RFoutBP1.3 RFoutBP1.4 RFoutBP2.2 RFoutBP2.3 RFoutBP2.4 U3.1(NC) U3.2(NC) U3.3(FS1) U3.4(FS2) U3.6(GND) U3.8(GND) U3.10(GND) U3.15(FS3) U3.16(FS4) U3.17(FS5) U3.18(FS6) U3.19(FS7) U3.20(FS8) U3.23(GND) U3.24(GND) U3.28(GND) U3.31(GND) U3.33(NC) U3.35(GND) U3.38(GND) U3.40(GND) U3.46(NC) U3.47(NC) U3.48(NC) U3.49(NC) U3.50(NC) U3.51(GND) U3.54(GND) U3.58(NC) U3.60(GND) U3.61(GND) U3.62(NC) U3.63(NC) U3.64(NC) U3.65(PAD) U4.1(NC) U4.2(NC) U4.3(FS1) U4.4(FS2) U4.6(GND) U4.8(GND) U4.10(GND) U4.15(FS3) U4.16(FS4) U4.17(FS5) U4.18(FS6) U4.19(FS7) U4.20(FS8) U4.23(GND) U4.24(GND) U4.28(GND) U4.31(GND) U4.33(NC) U4.35(GND) U4.38(GND) U4.40(GND) U4.46(NC) U4.47(NC) U4.48(NC) U4.49(NC) U4.50(NC) U4.51(GND) U4.54(GND) U4.58(NC) U4.60(GND) U4.61(GND) U4.62(NC) U4.63(NC) U4.64(NC) U4.65(PAD)
P3V3_LMX: C51.2 C52.2 C53.2 C54.2 C121.2 C122.2 C123.2 C127.2 R83.1 R85.1 R87.1 R88.1 R89.2 R90.1 R91.2 R251.1 R253.2 R254.2 R255.1 R256.1 R257.1 R274.1 Vcc_TP1.1 Vcc_TP2.1
ADC_CLK1+: C44.2 R82.1 U3.37(RFOUTAP)
ADC_CLK1-: C48.2 R86.2 U3.36(RFOUTAM)
ADC_CLK2+: C118.2 R258.1 U4.37(RFOUTAP)
ADC_CLK2-: C141.2 R260.2 U4.36(RFOUTAM)
ADC_SYSREF1+: C57.2 R93.1 U3.29(RFOUTBN/SYSREFOUTN)
ADC_SYSREF1-: C64.2 R97.2 U3.30(RFOUTBO/SYSREFOUTP)
ADC_SYSREF2+: C142.2 R315.1 U4.29(RFOUTBN/SYSREFOUTN)
ADC_SYSREF2-: C192.2 R327.2 U4.30(RFOUTBO/SYSREFOUTP)
DCLKout0*_N: R242.2 ; off-sheet DCLKout0*_N
DCLKout0*_P: R238.2 ; off-sheet DCLKout0*_P
DCLKout0_LMK_N: R236.2 ; off-sheet DCLKout0_LMK_N
DCLKout0_LMK_P: R234.2 ; off-sheet DCLKout0_LMK_P
DCLKout2*_N: R350.2 ; off-sheet DCLKout2*_N
DCLKout2*_P: R325.2 ; off-sheet DCLKout2*_P
DCLKout2_LMK_N: R275.2 ; off-sheet DCLKout2_LMK_N
DCLKout2_LMK_P: R248.2 ; off-sheet DCLKout2_LMK_P
J21: J21.1 R246.2
J22: J22.1 R249.2
J24: J24.1 R358.2
J26: J26.1 R360.2
LMK_LMX_CLK: U3.26(SCK) U4.26(SCK) ; off-sheet LMK_LMX_CLK
LMK_LMX_DATA: U3.27(SDI) U4.27(SDI) ; off-sheet LMK_LMX_DATA
LMX1_CSb: U3.39(CSB) ; off-sheet LMX1_CSb
LMX1_OSCin+: C71.2 U3.12(OSCINP)
LMX1_OSCin-: C72.2 U3.13(OSCINM)
LMX1_SDO: R102.2 ; off-sheet LMX1_SDO
LMX1_SYNC: R247.2 ; off-sheet LMX1_SYNC
LMX1_SYSREFREQ: R245.2 ; off-sheet LMX1_SYSREFREQ
LMX2_CSb: U4.39(CSB) ; off-sheet LMX2_CSb
LMX2_OSCin+: C191.2 U4.12(OSCINP)
LMX2_OSCin-: C195.2 U4.13(OSCINM)
LMX2_SDO: R313.2 ; off-sheet LMX2_SDO
LMX2_SYNC: R359.2 ; off-sheet LMX2_SYNC
LMX2_SYSREFREQ: R355.2 ; off-sheet LMX2_SYSREFREQ
LMX2615-SP_1_REF_N: R243.2 ; off-sheet LMX2615-SP_1_REF_N
LMX2615-SP_1_REF_P: R239.2 ; off-sheet LMX2615-SP_1_REF_P
LMX2615-SP_2_REF_N: R352.2 ; off-sheet LMX2615-SP_2_REF_N
LMX2615-SP_2_REF_P: R331.2 ; off-sheet LMX2615-SP_2_REF_P
MUXout1: R102.1 R105.2 U3.32(MUXOUT) ; port MUXout1
MUXout2: R313.1 R314.2 U4.32(MUXOUT) ; port MUXout2
OSCin1_N: OSCinM1.1 R244.2
OSCin1_P: OSCinP1.1 R240.2
OSCin2_N: OSCinM2.1 R353.2
OSCin2_P: OSCinP2.1 R332.2
RFoutA1_N: C48.1 R236.1 RFoutAM1.1
RFoutA1_P: C44.1 R234.1 RFoutAP1.1
RFoutA2_N: C141.1 R275.1 RFoutAM2.1
RFoutA2_P: C118.1 R248.1 RFoutAP2.1
RFoutB1_N: C57.1 R237.1 RFoutBM1.1
RFoutB1_P: C64.1 R241.1 RFoutBP1.1
RFoutB2_N: C142.1 R276.1 RFoutBM2.1
RFoutB2_P: C192.1 R347.1 RFoutBP2.1
SDCLKout1_LMK_N: R237.2 ; off-sheet SDCLKout1_LMK_N
SDCLKout1_LMK_P: R241.2 ; off-sheet SDCLKout1_LMK_P
SDCLKout3_LMK_N: R276.2 ; off-sheet SDCLKout3_LMK_N
SDCLKout3_LMK_P: R347.2 ; off-sheet SDCLKout3_LMK_P
NetC45_1: C45.1 L11.2 R82.2 R86.1
NetC46_2: C46.2 R91.1 U3.57(VCCVCO)
NetC47_2: C47.2 R89.1 U3.41(VCCVCO2)
NetC49_2: C49.2 R88.2 U3.25(VCCMASH)
NetC50_2: C50.2 R87.2 R235.2 U3.34(VCCBUF)
NetC55_2: C55.2 R85.2 U3.21(VCCCP)
NetC56_2: C56.2 R83.2 U3.11(VCCDIG)
NetC58_2: C58.2 R94.1 U3.55(VTUNE)
NetC59_1: C59.1 R94.2 R95.2 Vtune_TP1.1
NetC60_1: C60.1 C62.1 R95.1 U3.22(CPOUT)
NetC60_2: C60.2 R96.1
NetC61_1: C61.1 L12.2 R93.2 R97.1
NetC71_1: C71.1 R107.2 R109.2
NetC72_1: C72.1 R109.1 R112.1
NetC98_2: C98.2 U3.14(VREGIN)
NetC99_1: C99.1 U3.56(VREFVCO)
NetC100_2: C100.2 U3.59(VREGVCO)
NetC101_1: C101.1 U3.44(VREFVCO2)
NetC102_1: C102.1 U3.7(VBIASVCO)
NetC103_1: C103.1 U3.42(VBIASVCO2)
NetC104_1: C104.1 U3.53(VBIASVARAC)
NetC128_2: C128.2 R253.1 U4.57(VCCVCO)
NetC129_2: C129.2 R257.2 U4.11(VCCDIG)
NetC130_2: C130.2 R256.2 U4.21(VCCCP)
NetC131_2: C131.2 L18.2 R258.2 R260.1
NetC138_2: C138.2 R255.2 U4.25(VCCMASH)
NetC139_2: C139.2 R254.1 U4.41(VCCVCO2)
NetC140_2: C140.2 R251.2 R252.2 U4.34(VCCBUF)
NetC143_2: C143.2 U4.14(VREGIN)
NetC144_1: C144.1 U4.56(VREFVCO)
NetC145_2: C145.2 U4.59(VREGVCO)
NetC146_1: C146.1 C148.1 R320.1 U4.22(CPOUT)
NetC146_2: C146.2 R322.1
NetC147_1: C147.1 U4.44(VREFVCO2)
NetC149_1: C149.1 R320.2 R321.2 Vtune_TP2.1
NetC150_2: C150.2 R321.1 U4.55(VTUNE)
NetC151_1: C151.1 U4.7(VBIASVCO)
NetC152_1: C152.1 U4.42(VBIASVCO2)
NetC189_2: C189.2 L19.2 R315.2 R327.1
NetC190_1: C190.1 U4.53(VBIASVARAC)
NetC191_1: C191.1 R333.2 R349.2
NetC195_1: C195.1 R349.1 R354.1
NetCE_TP1_1: CE_TP1.1 R90.2 U3.5(CE)
NetCE_TP2_1: CE_TP2.1 R274.2 U4.5(CE)
NetD5_1: D5.1(A) R105.1
NetD6_1: D6.1(A) R314.1
NetR104_1: R104.1 R107.1 R238.1 R239.1 R240.1
NetR112_2: R112.2 R113.2 R242.1 R243.1 R244.1
NetR213_1: R213.1 R245.1 R246.1 U3.43(SYSREFREQ)
NetR214_1: R214.1 R247.1 R249.1 U3.9(SYNC)
NetR325_1: R325.1 R331.1 R332.1 R333.1 R348.1
NetR334_1: R334.1 R355.1 R358.1 U4.43(SYSREFREQ)
NetR342_1: R342.1 R359.1 R360.1 U4.9(SYNC)
NetR350_1: R350.1 R351.2 R352.1 R353.1 R354.2
NetRMPCLK1_1: RMPCLK1.1 U3.45(RAMPCLK/TRIG1)
NetRMPCLK2_1: RMPCLK2.1 U4.45(RAMPCLK/TRIG1)
NetRMPDIR1_1: RMPDIR1.1 U3.52(RAMPDIR/TRIG2)
NetRMPDIR2_1: RMPDIR2.1 U4.52(RAMPDIR/TRIG2)

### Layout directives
differential pair; differential pair class 100ohm: DCLKout0*_N, DCLKout0*_P, DCLKout0_LMK_N, DCLKout0_LMK_P, DCLKout2*_N, DCLKout2*_P, DCLKout2_LMK_N, DCLKout2_LMK_P, LMX2615-SP_1_REF_N, LMX2615-SP_1_REF_P, LMX2615-SP_2_REF_N, LMX2615-SP_2_REF_P, OSCin1_N, OSCin1_P, OSCin2_N, OSCin2_P, RFoutA1_N, RFoutA1_P, RFoutA2_N, RFoutA2_P, RFoutB1_N, RFoutB1_P, RFoutB2_N, RFoutB2_P, SDCLKout1_LMK_N, SDCLKout1_LMK_P, SDCLKout3_LMK_N, SDCLKout3_LMK_P

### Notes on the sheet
- RF PLL Synthesizer
- TI Datasheet <http://www.ti.com/lit/gpn/lmx2615-sp>
- LMX2615-SP <http://www.ti.com/product/LMX2615-SP>
- SMD-5962-17236 <https://landandmaritimeapps.dla.mil/Downloads/MilSpec/Smd/17236.pdf>
- (near R96) External Loop Filter
- Oscillator (Reference) Input
- (near R322) External Loop Filter

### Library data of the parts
C44 C45 C48 C57 C61 C64 C118 C131 C141 C142 C189 C192 = CMP-0006210-2: as C92 on sheet TIDA-010191-E2_CDCLVP111
C46 C47 C49 C55 C56 C128-C130 C138 C139 = CMP-0007037-4: CAP, CERM, 1 uF, 16 V, +/- 10%, X7R, 0603; Manufacturer: TDK; PartNumber: C1608X7R1C105K080AC; ESR_ohm: 5.7m; Polarized: N; TaMax_C: 125°C; TaMin_C: -55°C; VDC_V: 16V; Value: 1uF; Value1: 0.0057 ohm; U/M: EA; SizeArea_mm2: 1.28; SizeAreaWB_mm2: 4.68; SizeX_mm: 1.6; SizeY_mm: 0.8; SizeZ_mm: 1; AEC Category: Q200
C50 C140 = CMP-0006808-4: CAP, CERM, 0.1 uF, 16 V, +/- 5%, X7R, 0603; Manufacturer: AVX; PartNumber: 0603YC104JAT2A; ESR_ohm: 0.039; Polarized: N; TaMax_C: 125°C; TaMin_C: -55°C; VDC_V: 16V; Value: 0.1uF; Value1: 0.039 ohm; U/M: EA; SizeAreaWB_mm2: 4.68; SizeZ_mm: 1; SizeX_mm: 1.6; SizeY_mm: 0.8; SizeArea_mm2: 1.28; AEC Category: Q200
C51 C54 C121 C127 = CMP-0006808-4: CAP, CERM, 0.1 uF, 16 V, +/- 5%, X7R, 0603; Manufacturer: AVX; PartNumber: 0603YC104JAT2A; ESR_ohm: 0.039; Polarized: N; TaMax_C: 125°C; TaMin_C: -55°C; VDC_V: 16V; Cap_F: 100nF; Value: 0.1uF; Value1: 0.039 ohm; U/M: EA; AEC Category: Q200; SizeArea_mm2: 1.28; SizeAreaWB_mm2: 4.68; SizeX_mm: 1.6; SizeY_mm: 0.8; SizeZ_mm: 1
C52 C53 C122 C123 = CMP-0007732-2: CAP, CERM, 10 uF, 10 V, +/- 10%, X5R, 0805; Manufacturer: Kemet; PartNumber: C0805C106K8PACTU; Cap_Case: 0805; ESR_ohm: 3m; IRMS_A: 11.43A; Polarized: N; TaMax_C: 85°C; TaMin_C: -55°C; Cap_F: 10µF; Value: 10uF; U/M: EA; Value1: 0.003 ohm; SizeAreaWB_mm2: 6.75; SizeZ_mm: 1.45; SizeX_mm: 2; SizeY_mm: 1.25; SizeArea_mm2: 2.5; AEC Category: Q200
C58 C150 = CMP-0007192-4: CAP, CERM, 1800 pF, 50 V, +/- 5%, C0G/NP0, 0603; Manufacturer: MuRata; PartNumber: GRM1885C1H182JA01D; Polarized: N; TaMax_C: 125°C; TaMin_C: -55°C; VDC_V: 50V; Cap_F: 1.8nF; Value: 1800pF; Value1: Unknown; U/M: EA; SizeArea_mm2: 1.28; SizeAreaWB_mm2: 4.68; SizeX_mm: 1.6; SizeY_mm: 0.8; SizeZ_mm: 1; AEC Category: Q200
C59 C149 = CMP-0007262-4: CAP, CERM, 300 pF, 100 V, +/- 5%, C0G/NP0, 0603; Manufacturer: MuRata; PartNumber: GRM1885C2A301JA01D; Polarized: N; TaMax_C: 125°C; TaMin_C: -55°C; Value: 300pF; Value1: Unknown; U/M: EA; SizeAreaWB_mm2: 4.68; SizeZ_mm: 1; SizeX_mm: 1.6; SizeY_mm: 0.8; SizeArea_mm2: 1.28; AEC Category: Q200
C60 C146 = CMP-0007460-5: CAP, CERM, 0.056 uF, 50 V, +/- 10%, X7R, 0603; Manufacturer: MuRata; PartNumber: GRM188R71H563KA93D; Polarized: N; TaMax_C: 125°C; TaMin_C: -55°C; VDC_V: 50V; Cap_F: 56nF; Value1: Unknown; U/M: EA; AEC Category: Q200; SizeArea_mm2: 1.28; SizeAreaWB_mm2: 4.68; SizeX_mm: 1.6; SizeY_mm: 0.8; SizeZ_mm: 1; MFG_Status: TI_Obsolete
C62 C148 = CMP-0064973-4: CAP, CERM, 1500 pF, 50 V,+/- 5%, C0G/NP0, 0603; Manufacturer: MuRata; PartNumber: GRM1885C1H152JA01J; Polarized: N; TaMax_C: 125°C; TaMin_C: -55°C; VDC_V: 50V; Cap_F: 1.5nF; Value: 1500pF; Value1: Unknown; U/M: EA; AEC Category: Q200; SizeArea_mm2: 1.28; SizeAreaWB_mm2: 4.68; SizeX_mm: 1.6; SizeY_mm: 0.8; SizeZ_mm: 1
C71 C72 C191 C195 = CMP-0006808-4: CAP, CERM, 0.1 uF, 16 V, +/- 5%, X7R, 0603; Manufacturer: AVX; PartNumber: 0603YC104JAT2A; Cap_Case: 0603; ESR_ohm: 0.039; Polarized: N; TaMax_C: 125°C; TaMin_C: -55°C; VDC_V: 16V; Cap_F: 100nF; Value: 0.1uF; Value1: 0.039 ohm; U/M: EA; AEC Category: Q200; SizeArea_mm2: 1.28; SizeAreaWB_mm2: 4.68; SizeX_mm: 1.6; SizeY_mm: 0.8; SizeZ_mm: 1
C98 C100 C143 C145 = CMP-0007037-4: CAP, CERM, 1 uF, 16 V, +/- 10%, X7R, 0603; Manufacturer: TDK; PartNumber: C1608X7R1C105K080AC; ESR_ohm: 5.7m; Polarized: N; TaMax_C: 125°C; TaMin_C: -55°C; VDC_V: 16V; Value: 1uF; U/M: EA; Value1: 0.0057 ohm; AEC Category: Q200; SizeAreaWB_mm2: 4.68; SizeZ_mm: 1; SizeX_mm: 1.6; SizeY_mm: 0.8; SizeArea_mm2: 1.28
C99 C101-C104 C144 C147 C151 C152 C190 = CMP-0007003-5: CAP, CERM, 10 uF, 10 V, +/- 20%, X5R, 0603; Manufacturer: TDK; PartNumber: C1608X5R1A106M080AC; ESR_ohm: 7.8m; IRMS_A: 1.85A; Polarized: N; TaMax_C: 85°C; TaMin_C: -55°C; VDC_V: 10V; Cap_F: 10µF; Value: 10uF; U/M: EA; Value1: 0.0078 ohm; AEC Category: Q200; SizeAreaWB_mm2: 4.68; SizeZ_mm: 1; SizeX_mm: 1.6; SizeY_mm: 0.8; SizeArea_mm2: 1.28
CE_TP1 CE_TP2 RMPCLK1 RMPCLK2 RMPDIR1 RMPDIR2 Vcc_TP1 Vcc_TP2 Vtune_TP1 Vtune_TP2 = CMP-0055144-2: Test Point, Compact, White, TH; Manufacturer: Keystone Electronics; CNHeader: FALSE; ContactFinish: Silver; CT: TRUE; Green_Lifecycle: Active; Green_REACh: Passed
D5 D6 = CMP-0002891-3: LED, Green, SMD; Manufacturer: Lite-On; PartNumber: LTST-C191TGKT; Type: InGaN; Vf_V: 3.2V; Io_A: 20mA; Value1: W
J21 J22 J24 J26 OSCinM1 OSCinM2 OSCinP1 OSCinP2 = CMP-0055819-1: Connector, SMA, TH; Manufacturer: Cinch Connectivity; CT: TRUE; CNHeader: FALSE; Green_Lifecycle: Not Set; Green_REACh: Incomplete
L11 L12 L18 L19 = CMP-0058614-1: Inductor, Multilayer, Air Core, 18 nH, 0.3 A, 0.36 ohm, SMD; PartNumber: LQG15HS18NJ02D; Manufacturer: MuRata; Value: 18nH; Imax_A: 300mA; Irms: 0.3A @ C rise; Isat: 0.3A @ % inductance drop; DCR_ohm: 0.36; Value2: 0.3A; AEC Category: Q200; Green_Lifecycle: Active; SizeAreaWB_mm2: 3; Green_REACh: Passed; SizeZ_mm: 0.55; SizeX_mm: 1; SizeY_mm: 0.5
R82 R86 R93 R97 R258 R260 R315 R327 = CMP-0026791-1: RES, 50, 0.1%, 0.05 W, 0402; PartNumber: FC0402E50R0BST1; Manufacturer: Vishay-Dale; Value: 50; Value_Code: 50R0; Power_W: 50mW; Value2: 0.05W; TempCo: 25 ppm/C; U/M: EA; SizeArea_mm2: 0.5; SizeX_mm: 1; SizeZ_mm: 0.6; AEC Category: Q200; AEC Qualified: N
R83 R85 R87-R89 R91 R235 R251-R257 = CMP-0025697-4: RES, 0, 5%, 0.1 W, AEC-Q200 Grade 0, 0603; Manufacturer: Vishay-Dale; PartNumber: CRCW06030000Z0EA; VDC_V: 75V; Power_W: 100mW; Value_Code: 0000; Value2: 0.1W; EIA_Code: E24; AEC Category: Q200; AEC Qualified: Y; SizeArea_mm2: 1.28; SizeX_mm: 1.6; SizeY_mm: 0.8; SizeZ_mm: 1; TempCo: 200 ppm/C
R90 R274 = CMP-0025698-4: RES, 100 k, 5%, 0.1 W, AEC-Q200 Grade 0, 0603; Manufacturer: Vishay-Dale; PartNumber: CRCW0603100KJNEA; VDC_V: 75V; Power_W: 100mW; Value: 100k; Value2: 0.1W; EIA_Code: E24; TempCo: 200 ppm/C; SizeArea_mm2: 1.28; SizeX_mm: 1.6; SizeY_mm: 0.8; SizeZ_mm: 1; AEC Category: Q200; AEC Qualified: Y; AEC Grade: 0
R94 R321 = CMP-0025904-5: RES, 270, 5%, 0.1 W, 0603; Manufacturer: Yageo; PartNumber: RC0603JR-07270RL; VDC_V: 75V; Power_W: 100mW; Value: 270; Value_Code: 270R; Value2: 0.1W; EIA_Code: E24; TempCo: 100 ppm/C; SizeArea_mm2: 1.28; SizeX_mm: 1.6; SizeY_mm: 0.8; SizeZ_mm: 1; AEC Category: Q200; AEC Qualified: N; SizeAreaWB_mm2: 4.68
R95 R107 R112 R320 R333 R354 = CMP-0025697-4: RES, 0, 5%, 0.1 W, AEC-Q200 Grade 0, 0603; Manufacturer: Vishay-Dale; PartNumber: CRCW06030000Z0EA; VDC_V: 75V; Power_W: 100mW; Value: 0; Value_Code: 0000; Value2: 0.1W; EIA_Code: E24; TempCo: 200 ppm/C; SizeArea_mm2: 1.28; SizeX_mm: 1.6; SizeY_mm: 0.8; SizeZ_mm: 1; AEC Category: Q200; AEC Qualified: Y
R96 R322 = CMP-0025710-4: RES, 120, 5%, 0.1 W, AEC-Q200 Grade 0, 0603; Manufacturer: Vishay-Dale; PartNumber: CRCW0603120RJNEA; VDC_V: 75V; Power_W: 100mW; Value: 120; Value_Code: 120R; Value2: 0.1W; TempCo: 200 ppm/C; EIA_Code: E24; SizeArea_mm2: 1.28; SizeX_mm: 1.6; SizeY_mm: 0.8; SizeZ_mm: 1; AEC Category: Q200; AEC Qualified: Y; AEC Grade: 0
R102 R109 R313 R349 = CMP-0021991-4: RES, 100, 1%, 0.1 W, AEC-Q200 Grade 0, 0603; Manufacturer: Vishay-Dale; PartNumber: CRCW0603100RFKEA; VDC_V: 75V; Power_W: 100mW; Value: 100; Value_Code: 100R; Value2: 0.1W; EIA_Code: E96; TempCo: 100 ppm/C; SizeArea_mm2: 1.28; SizeX_mm: 1.6; SizeY_mm: 0.8; SizeZ_mm: 1; AEC Category: Q200; AEC Qualified: Y; AEC Grade: 0
R104 R113 R348 R351 = CMP-0025825-4: RES, 51, 5%, 0.1 W, AEC-Q200 Grade 0, 0603; PartNumber: CRCW060351R0JNEA; Manufacturer: Vishay-Dale; Value: 51; Value_Code: 51R0; Power_W: 100mW; Value2: 0.1W; VDC_V: 75V; TempCo: 200 ppm/C; EIA_Code: E24; SizeArea_mm2: 1.28; SizeX_mm: 1.6; SizeY_mm: 0.8; SizeZ_mm: 1; AEC Category: Q200; AEC Qualified: Y; AEC Grade: 0
R105 R314 = CMP-0025912-5: RES, 330, 5%, 0.1 W, 0603; Manufacturer: Yageo; PartNumber: RC0603JR-07330RL; VDC_V: 75V; Power_W: 100mW; Value_Code: 330R; Value2: 0.1W; EIA_Code: E24; AEC Category: Q200; AEC Qualified: N; SizeArea_mm2: 1.28; SizeAreaWB_mm2: 4.68; SizeX_mm: 1.6; SizeY_mm: 0.8; SizeZ_mm: 1; TempCo: 100 ppm/C
R213 R214 R342 = CMP-0026769-2: RES, 10.0 k, 0.5%, 0.063 W, AEC-Q200 Grade 0, 0402; PartNumber: CRCW040210K0DHEDP; Manufacturer: Vishay-Dale; Value: 10.0k; Res_ohm: 10k; Value_Code: 10k0; Power_W: 63mW; Value2: 0.063W; VDC_V: 50V; TempCo: 50 ppm/C; SizeArea_mm2: 0.5; SizeX_mm: 1; SizeZ_mm: 0.6; EIA_Code: E192; AEC Category: Q200; AEC Qualified: Y; AEC Grade: 0
R234 R236-R249 R275 R276 R325 R331 R332 R347 R350 R352 R353 R355 R358-R360 = CMP-0026822-3: RES, 0, 5%, 0.063 W, AEC-Q200 Grade 0, 0402; PartNumber: CRCW04020000Z0ED; Manufacturer: Vishay-Dale; Value: 0; Value_Code: 0000; Power_W: 63mW; Value2: 0.063W; VDC_V: 50V; TempCo: 200 ppm/C; SizeArea_mm2: 0.5; SizeX_mm: 1; SizeZ_mm: 0.6; EIA_Code: E24; AEC Category: Q200; AEC Qualified: Y
R334 = CMP-0026769-2: RES, 10.0 k, 0.5%, 0.063 W, AEC-Q200 Grade 0, 0402; Manufacturer: Vishay-Dale; Value: 10.0k; Res_ohm: 10k; Value_Code: 10k0; Power_W: 63mW; Value2: 0.063W; VDC_V: 50V; TempCo: 50 ppm/C; SizeArea_mm2: 0.5; SizeX_mm: 1; SizeZ_mm: 0.6; EIA_Code: E192; AEC Category: Q200; AEC Qualified: Y; AEC Grade: 0
RFoutAM1 RFoutAM2 RFoutAP1 RFoutAP2 RFoutBM1 RFoutBM2 RFoutBP1 RFoutBP2 = CMP-0055844-3: as J7 on sheet TIDA-010191-E2_CDCLVP111
U3 U4 = CMP-0013512-3: Space Grade 40 MHz to 15 GHz Wideband Synthesizer with Phase Synchronization and JESD204B Support, HBD0064A (CFP-64); Manufacturer: Texas Instruments; CompType: IC; SizeZ_mm: 2.31; AEC Category: Q200; AEC Qualified: N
